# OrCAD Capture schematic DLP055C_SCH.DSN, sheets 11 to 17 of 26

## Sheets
11 P20 - RS232: size A3
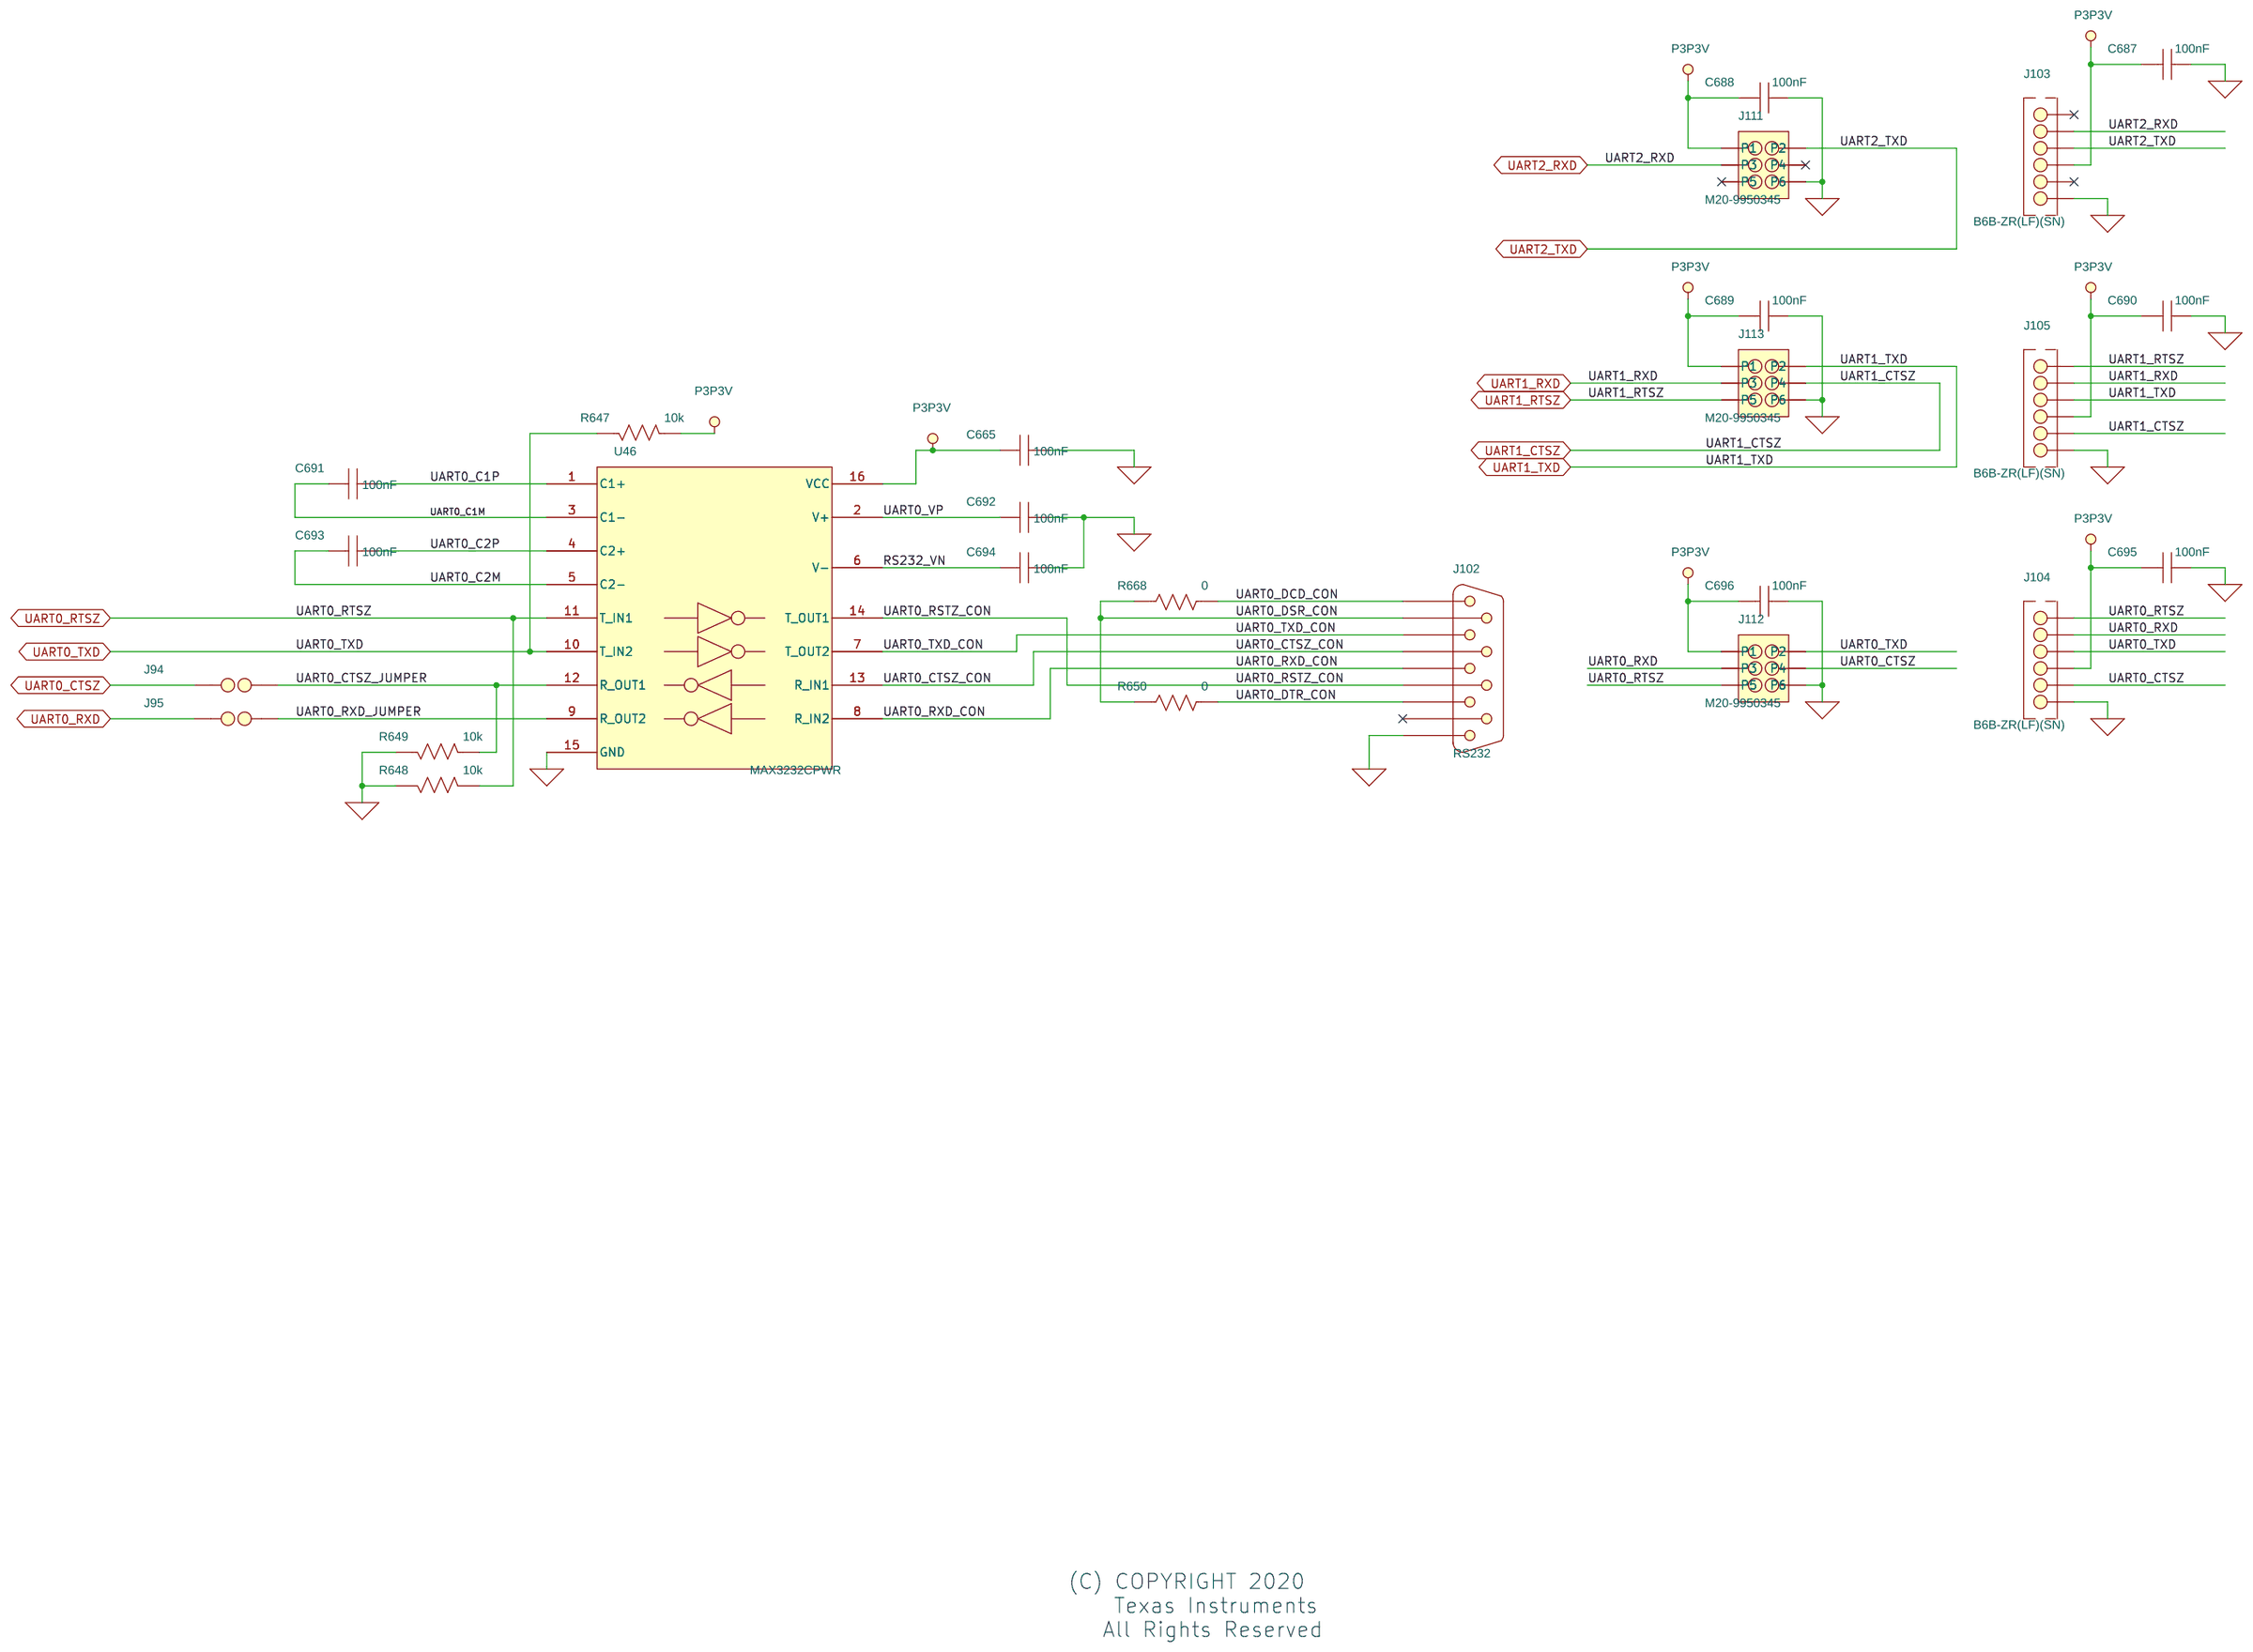
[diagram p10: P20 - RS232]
12 P14 - Actuator Driver: size A2
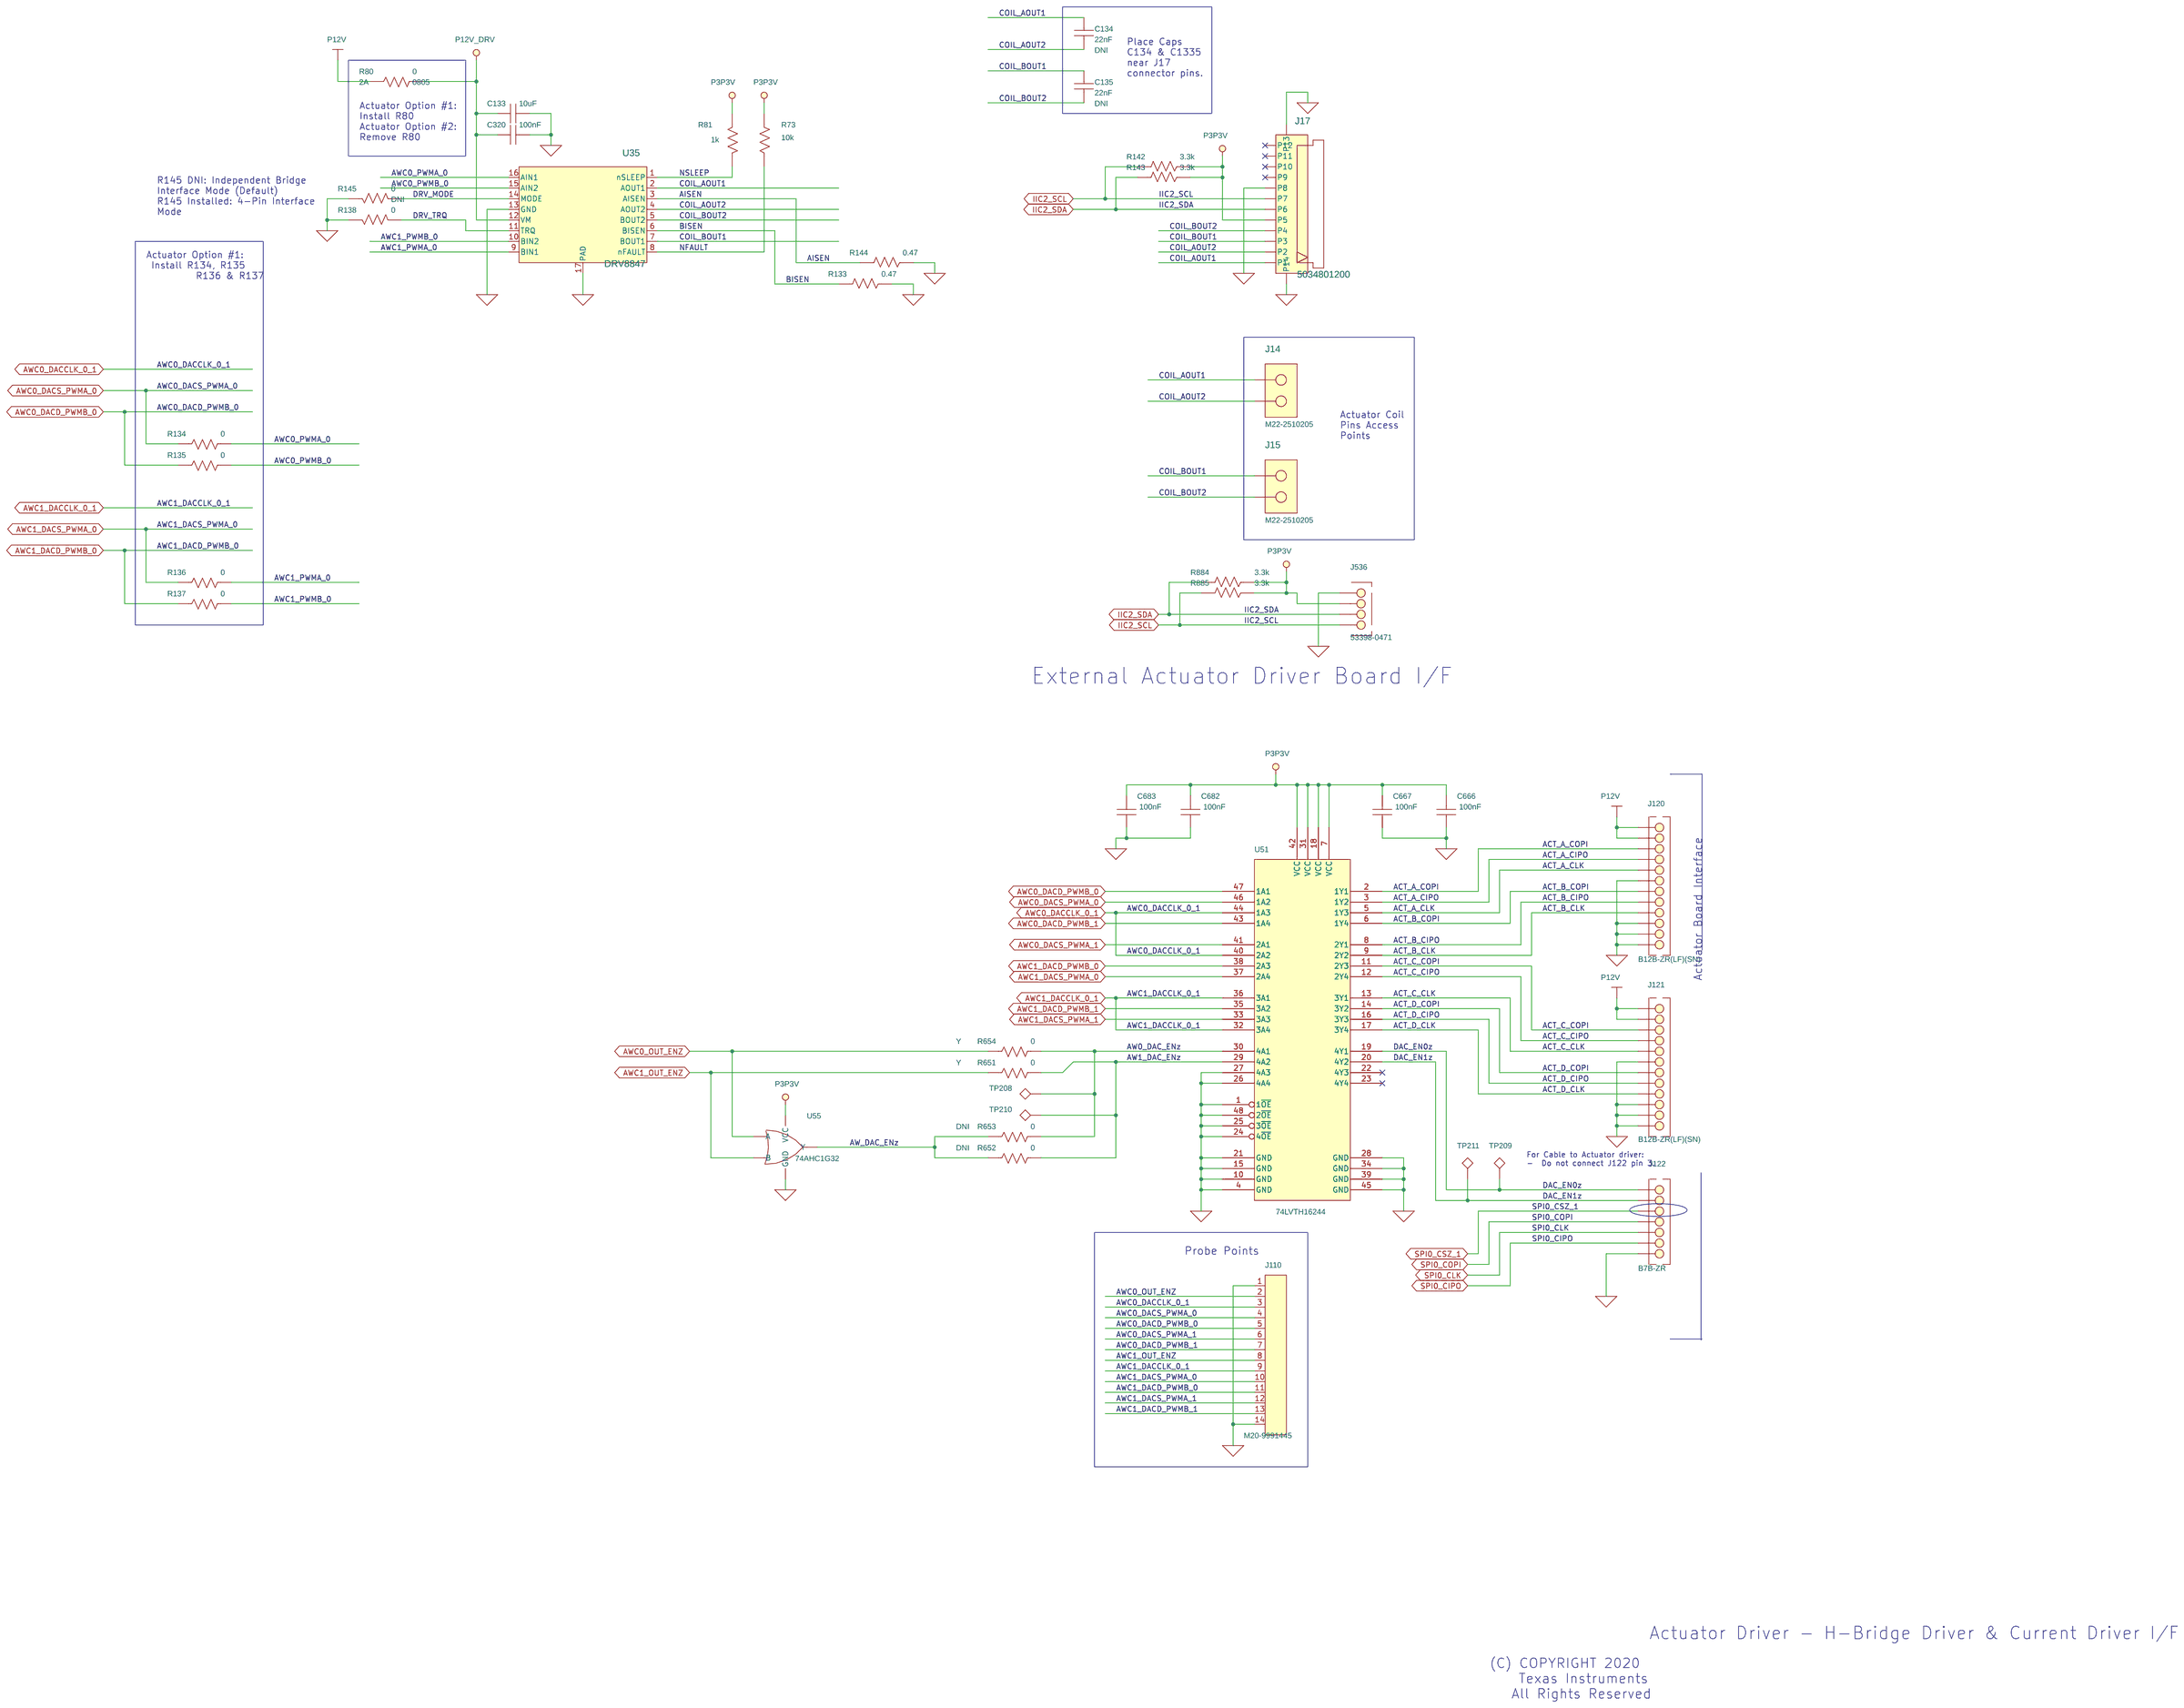
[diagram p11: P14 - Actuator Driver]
13 P01 - TITLE PAGE
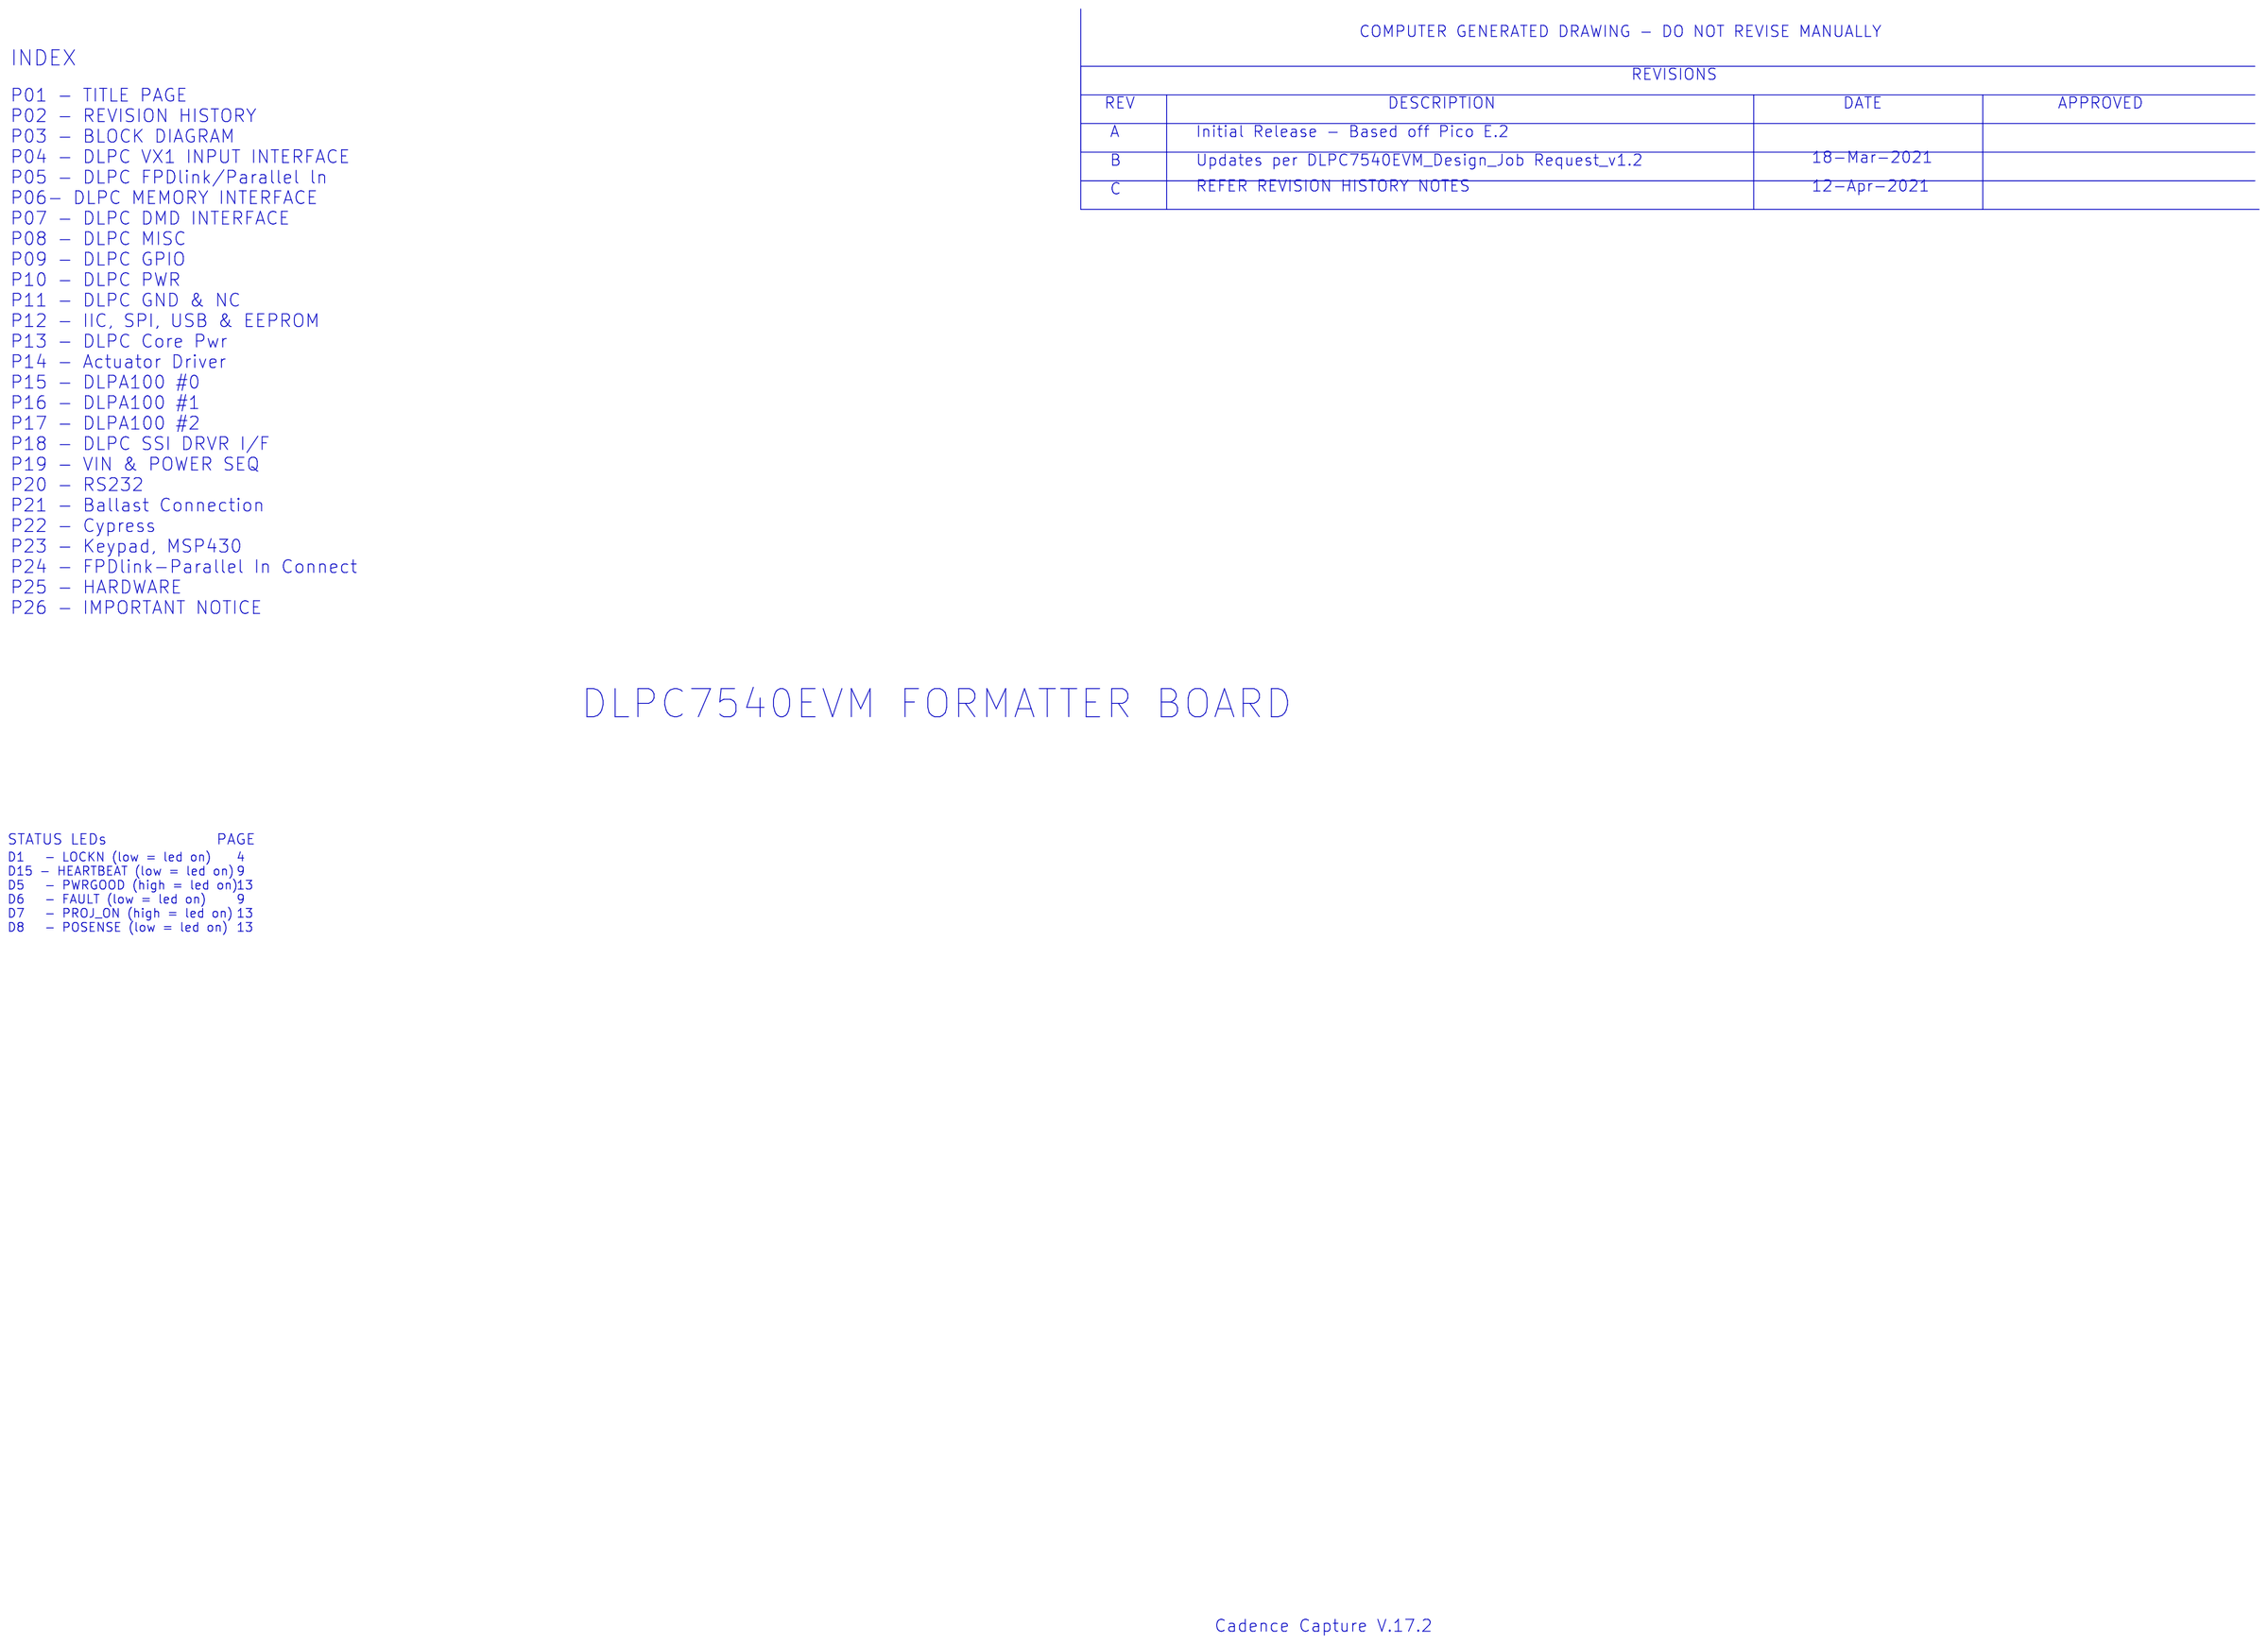
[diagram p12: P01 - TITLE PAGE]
14 P03 - BLOCK DIAGRAM
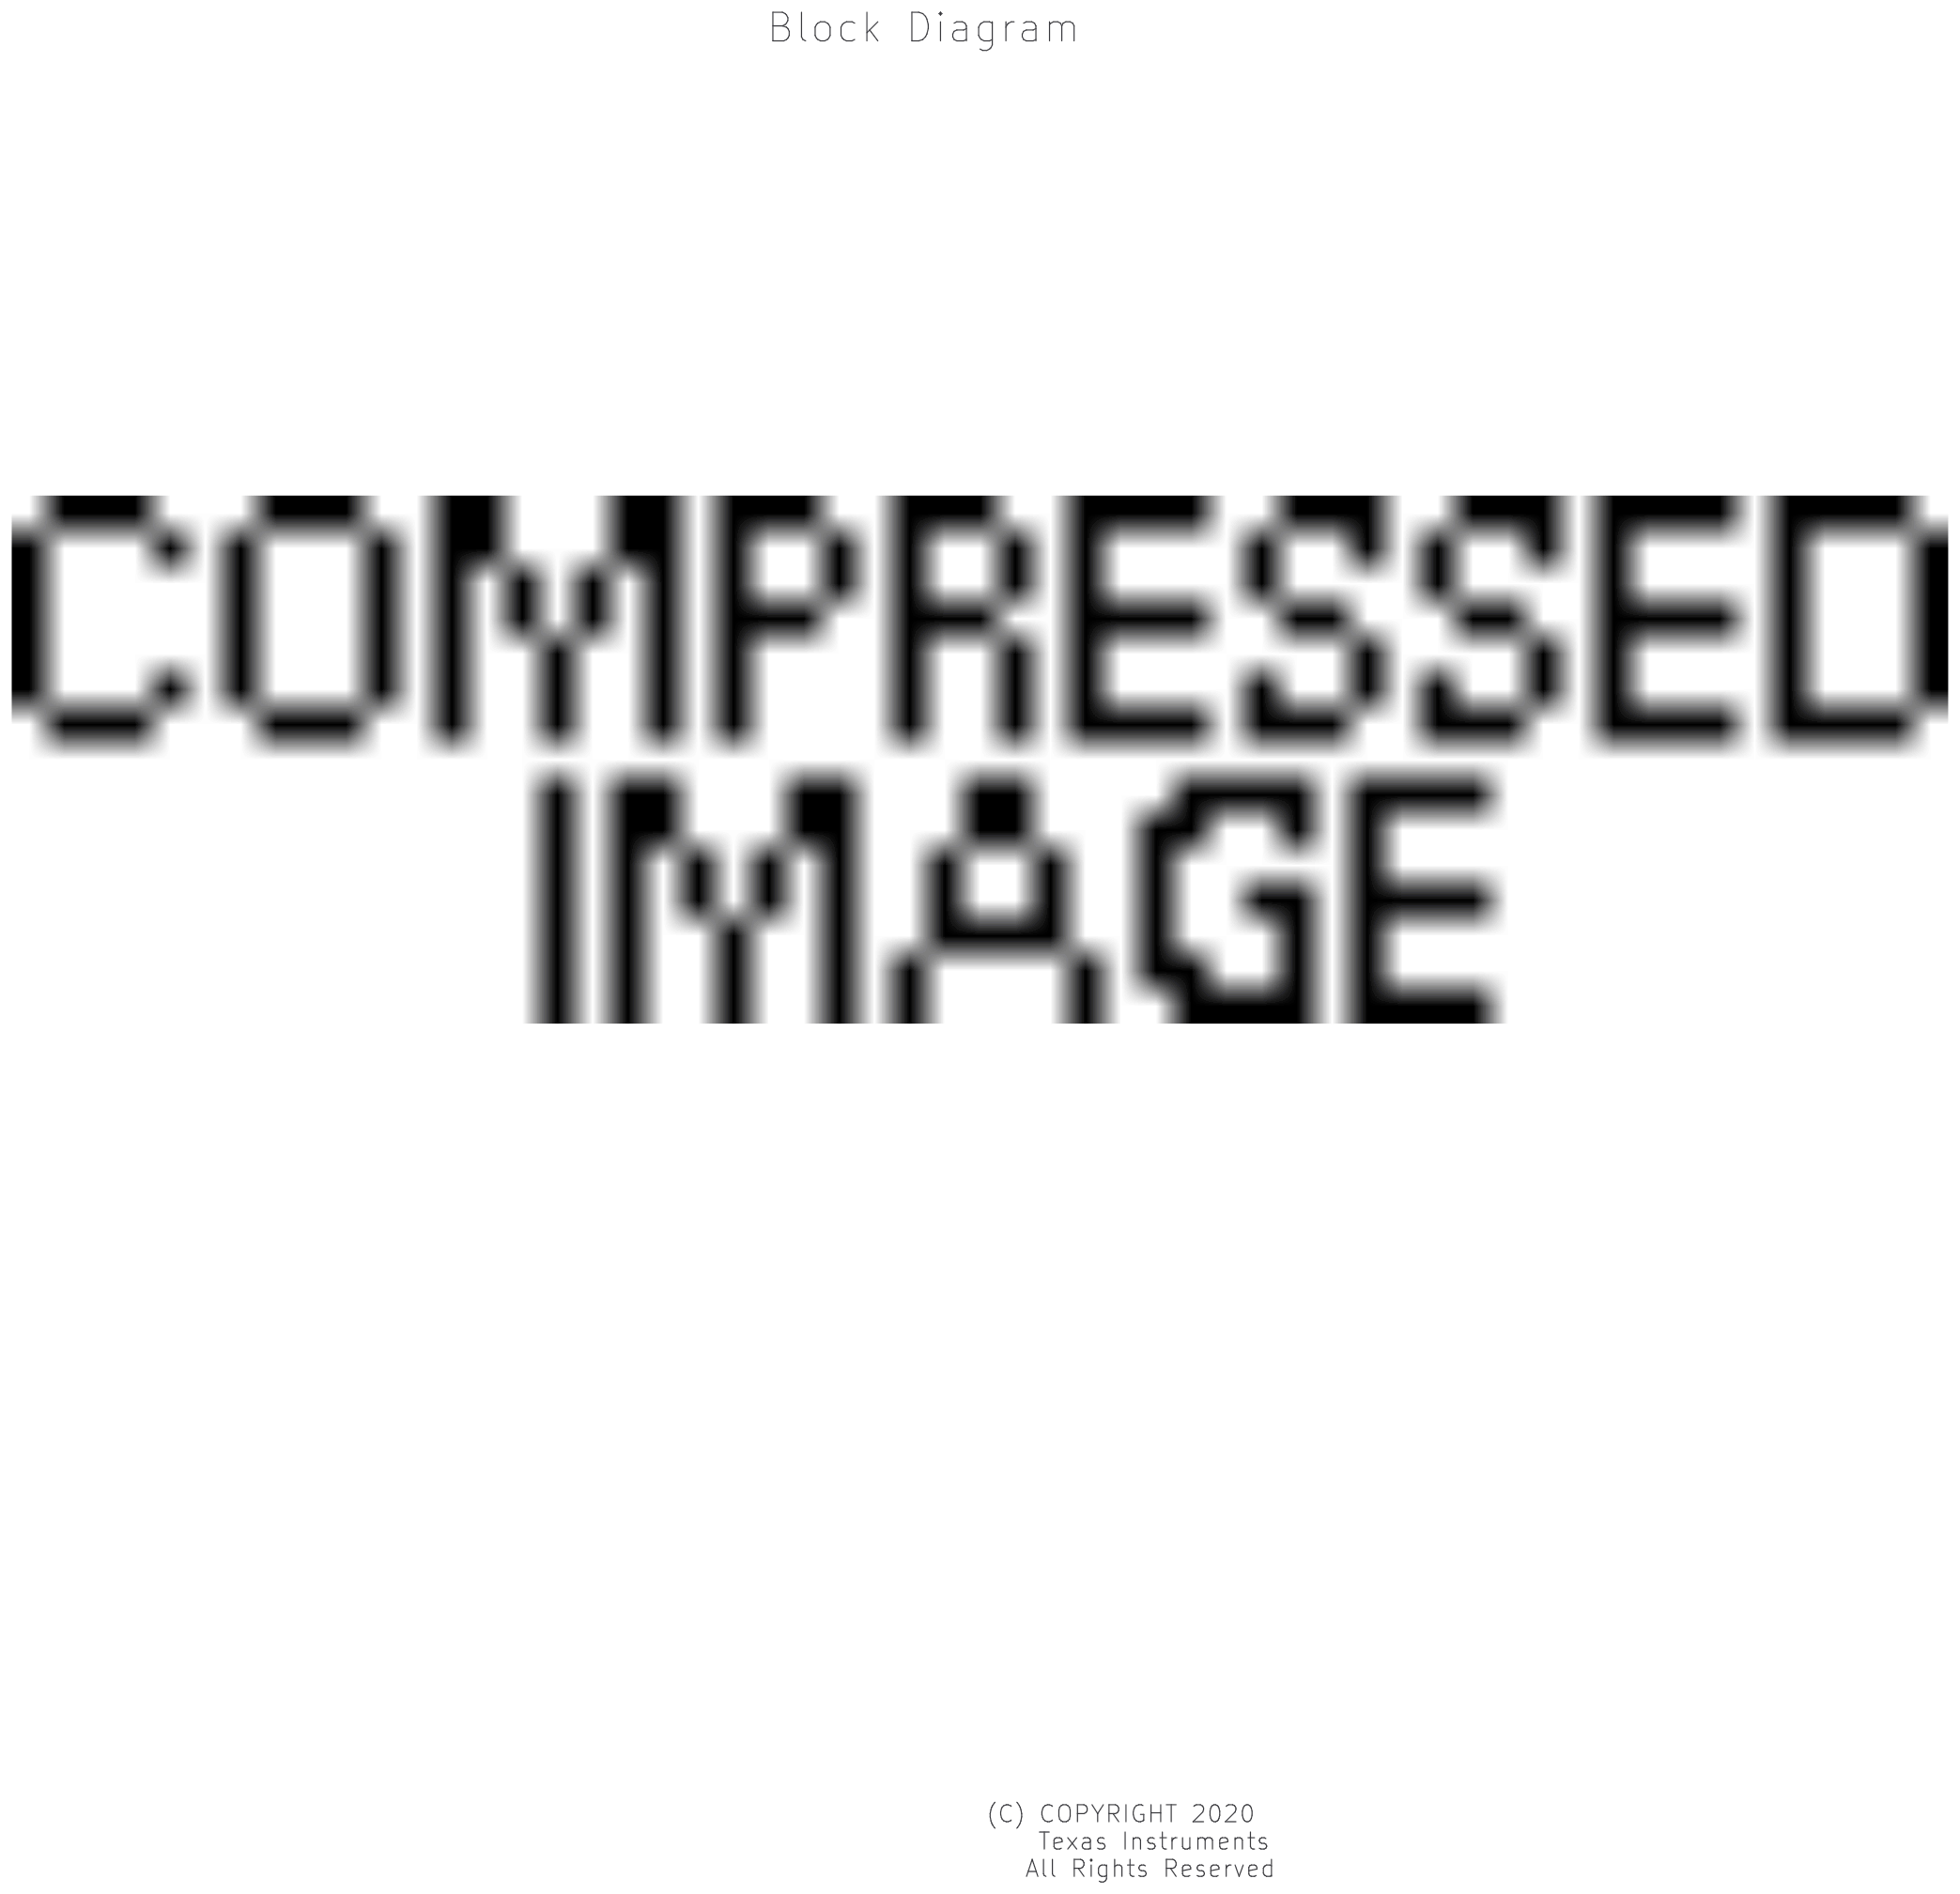
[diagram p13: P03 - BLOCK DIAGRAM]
15 P04 - DLPC VX1 INPUT INTERFACE: size A3
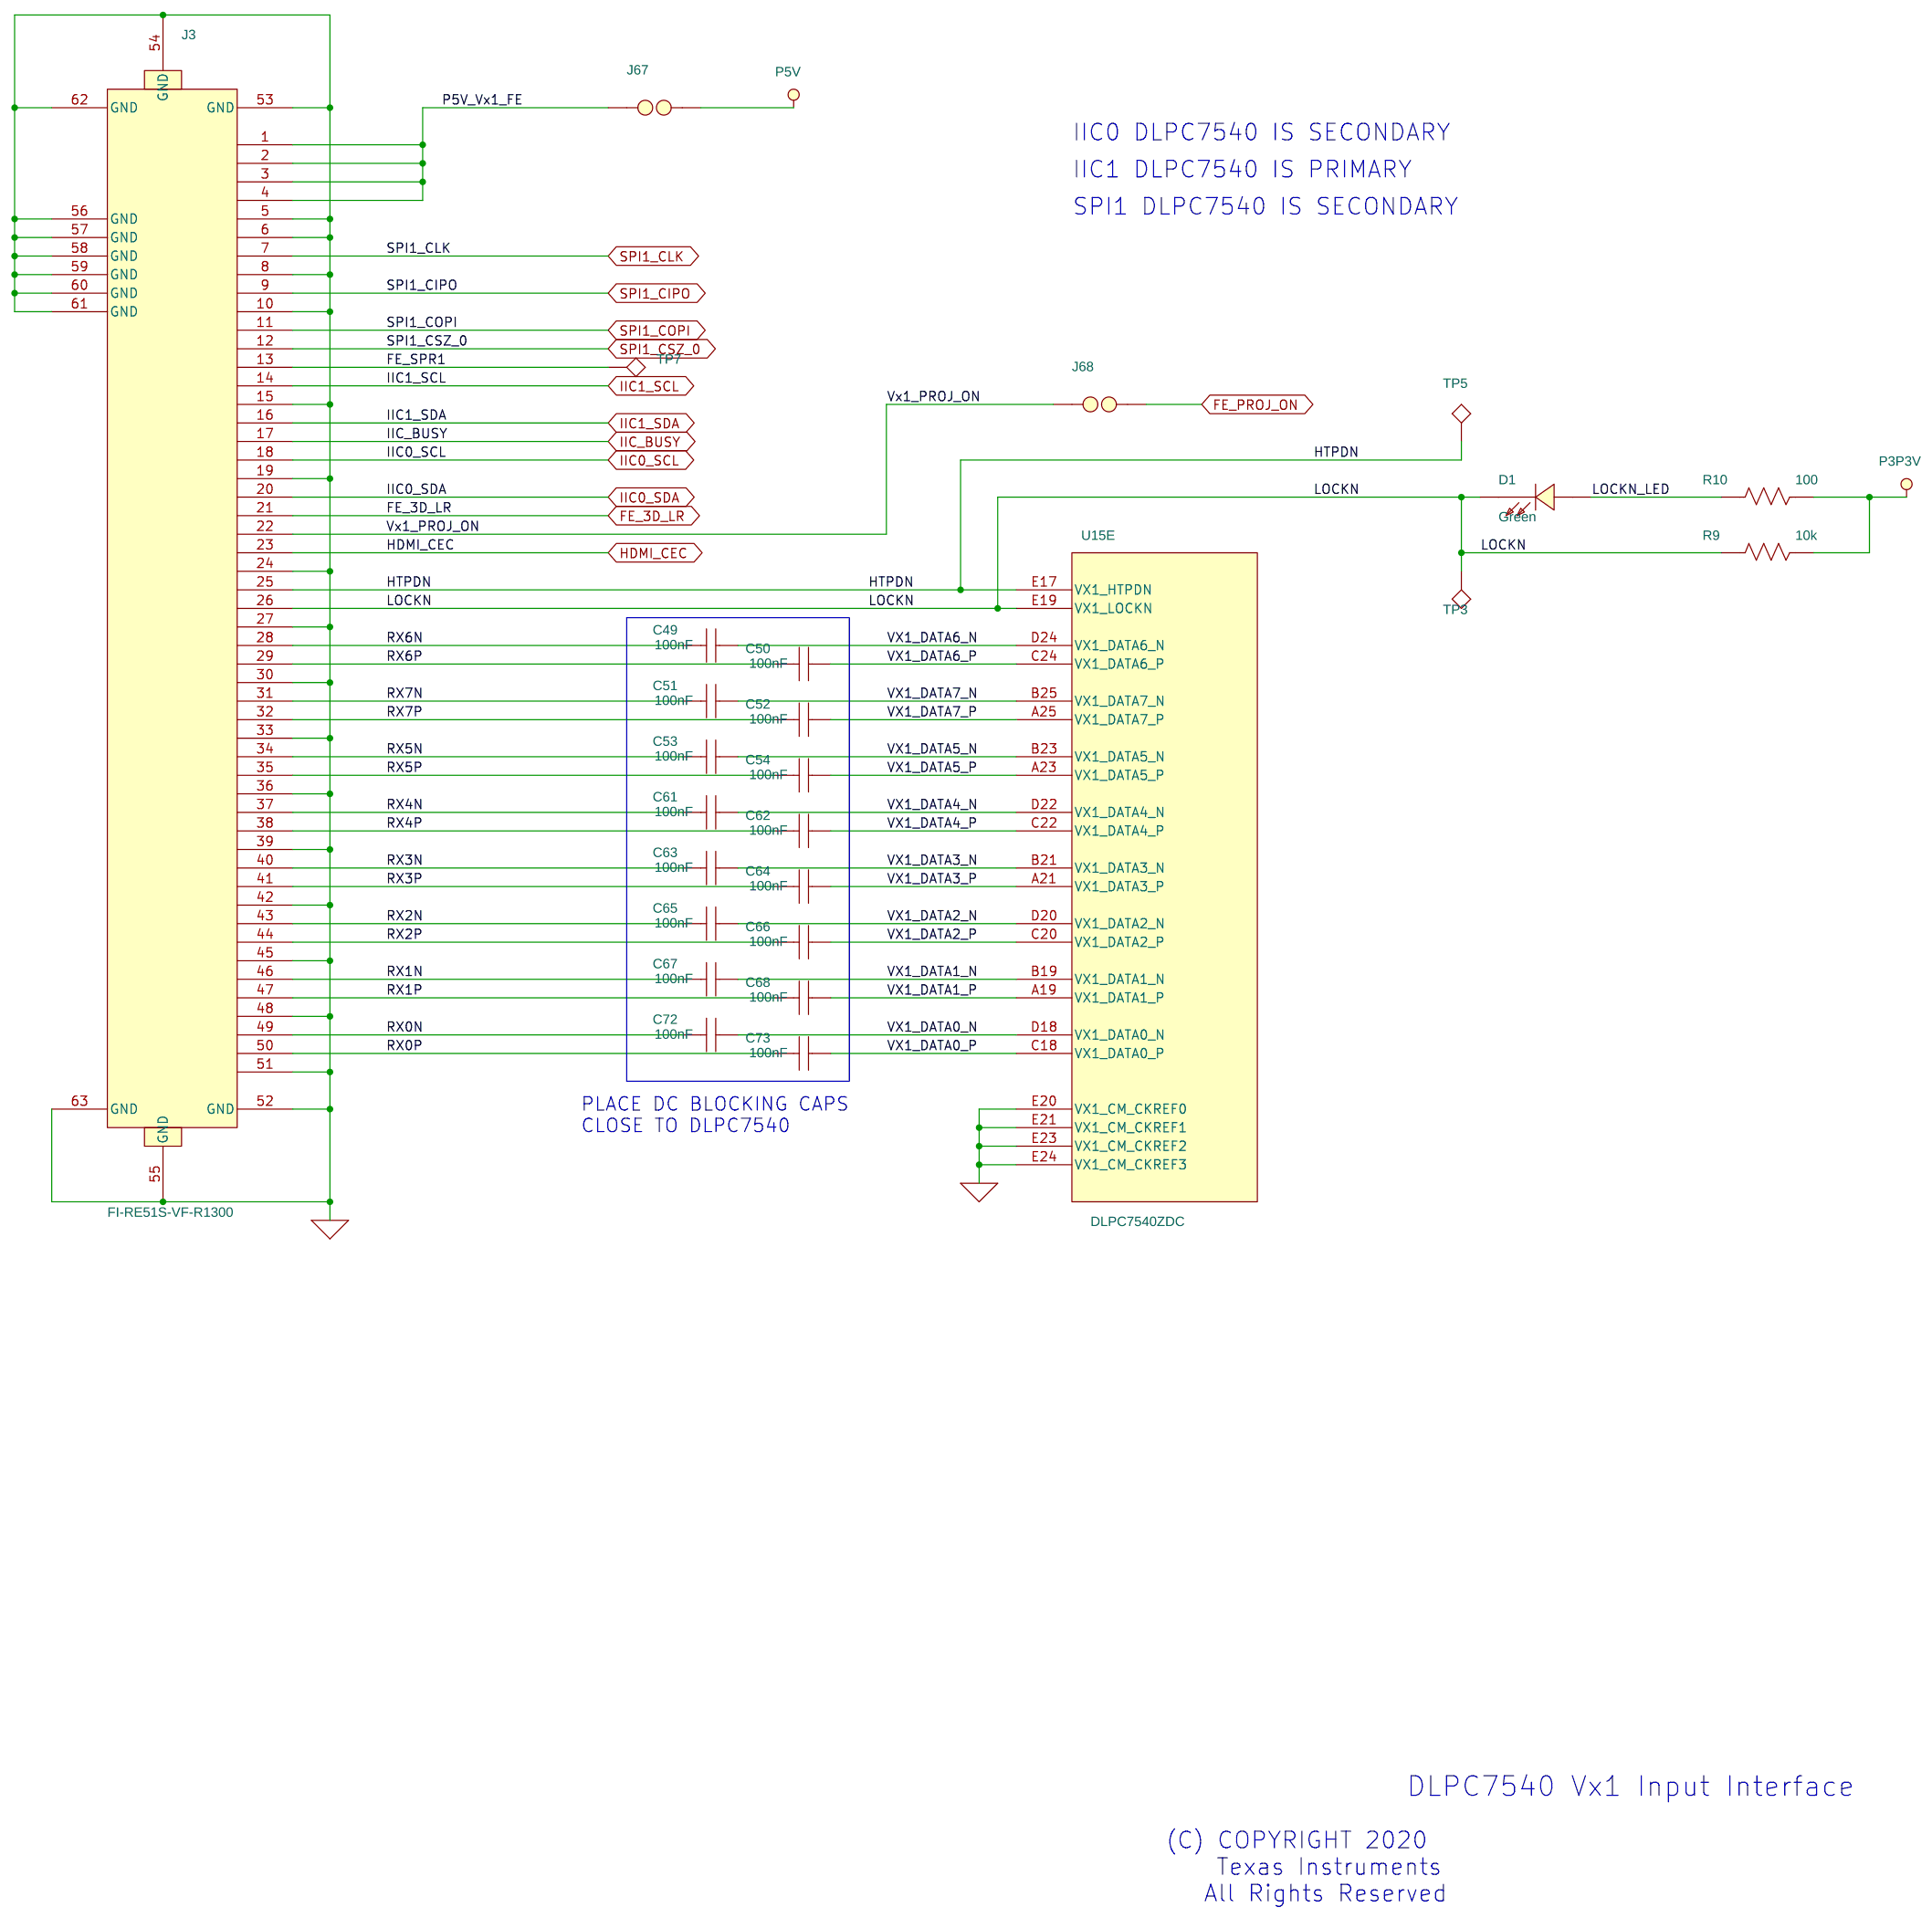
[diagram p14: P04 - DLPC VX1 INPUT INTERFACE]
16 P06- DLPC MEMORY INTERFACE: size A3
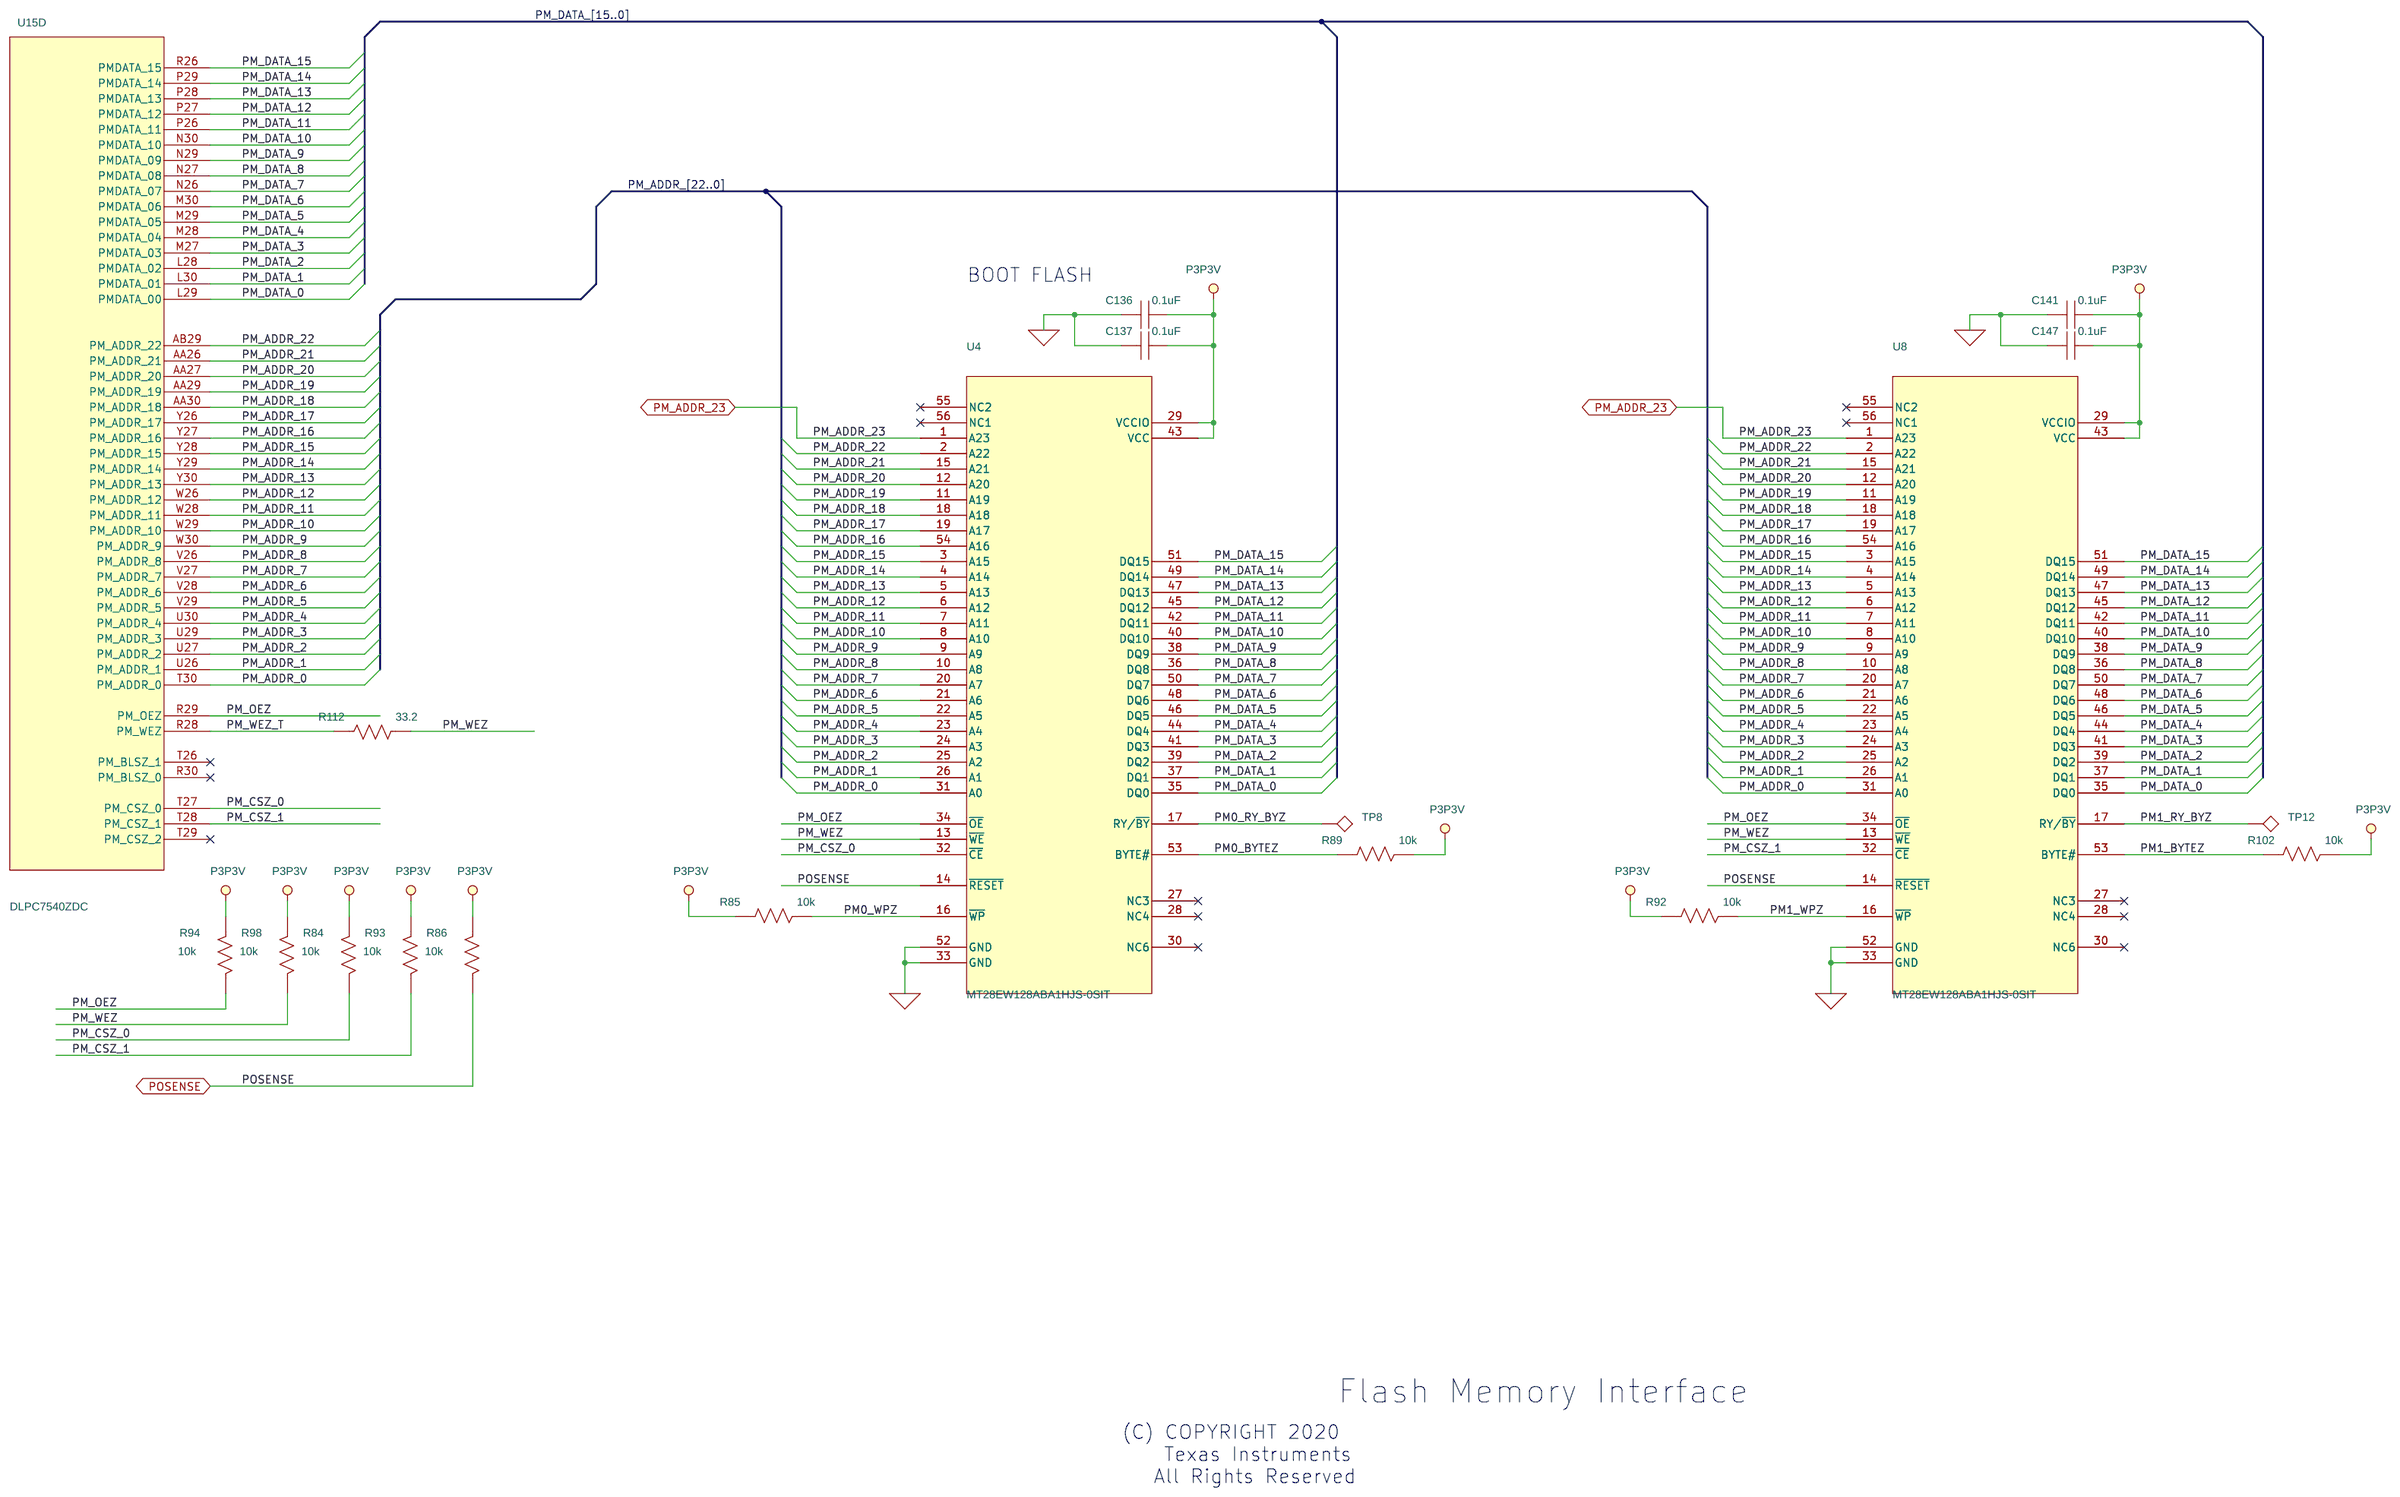
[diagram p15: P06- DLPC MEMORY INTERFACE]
17 P07 - DLPC DMD INTERFACE: size A3
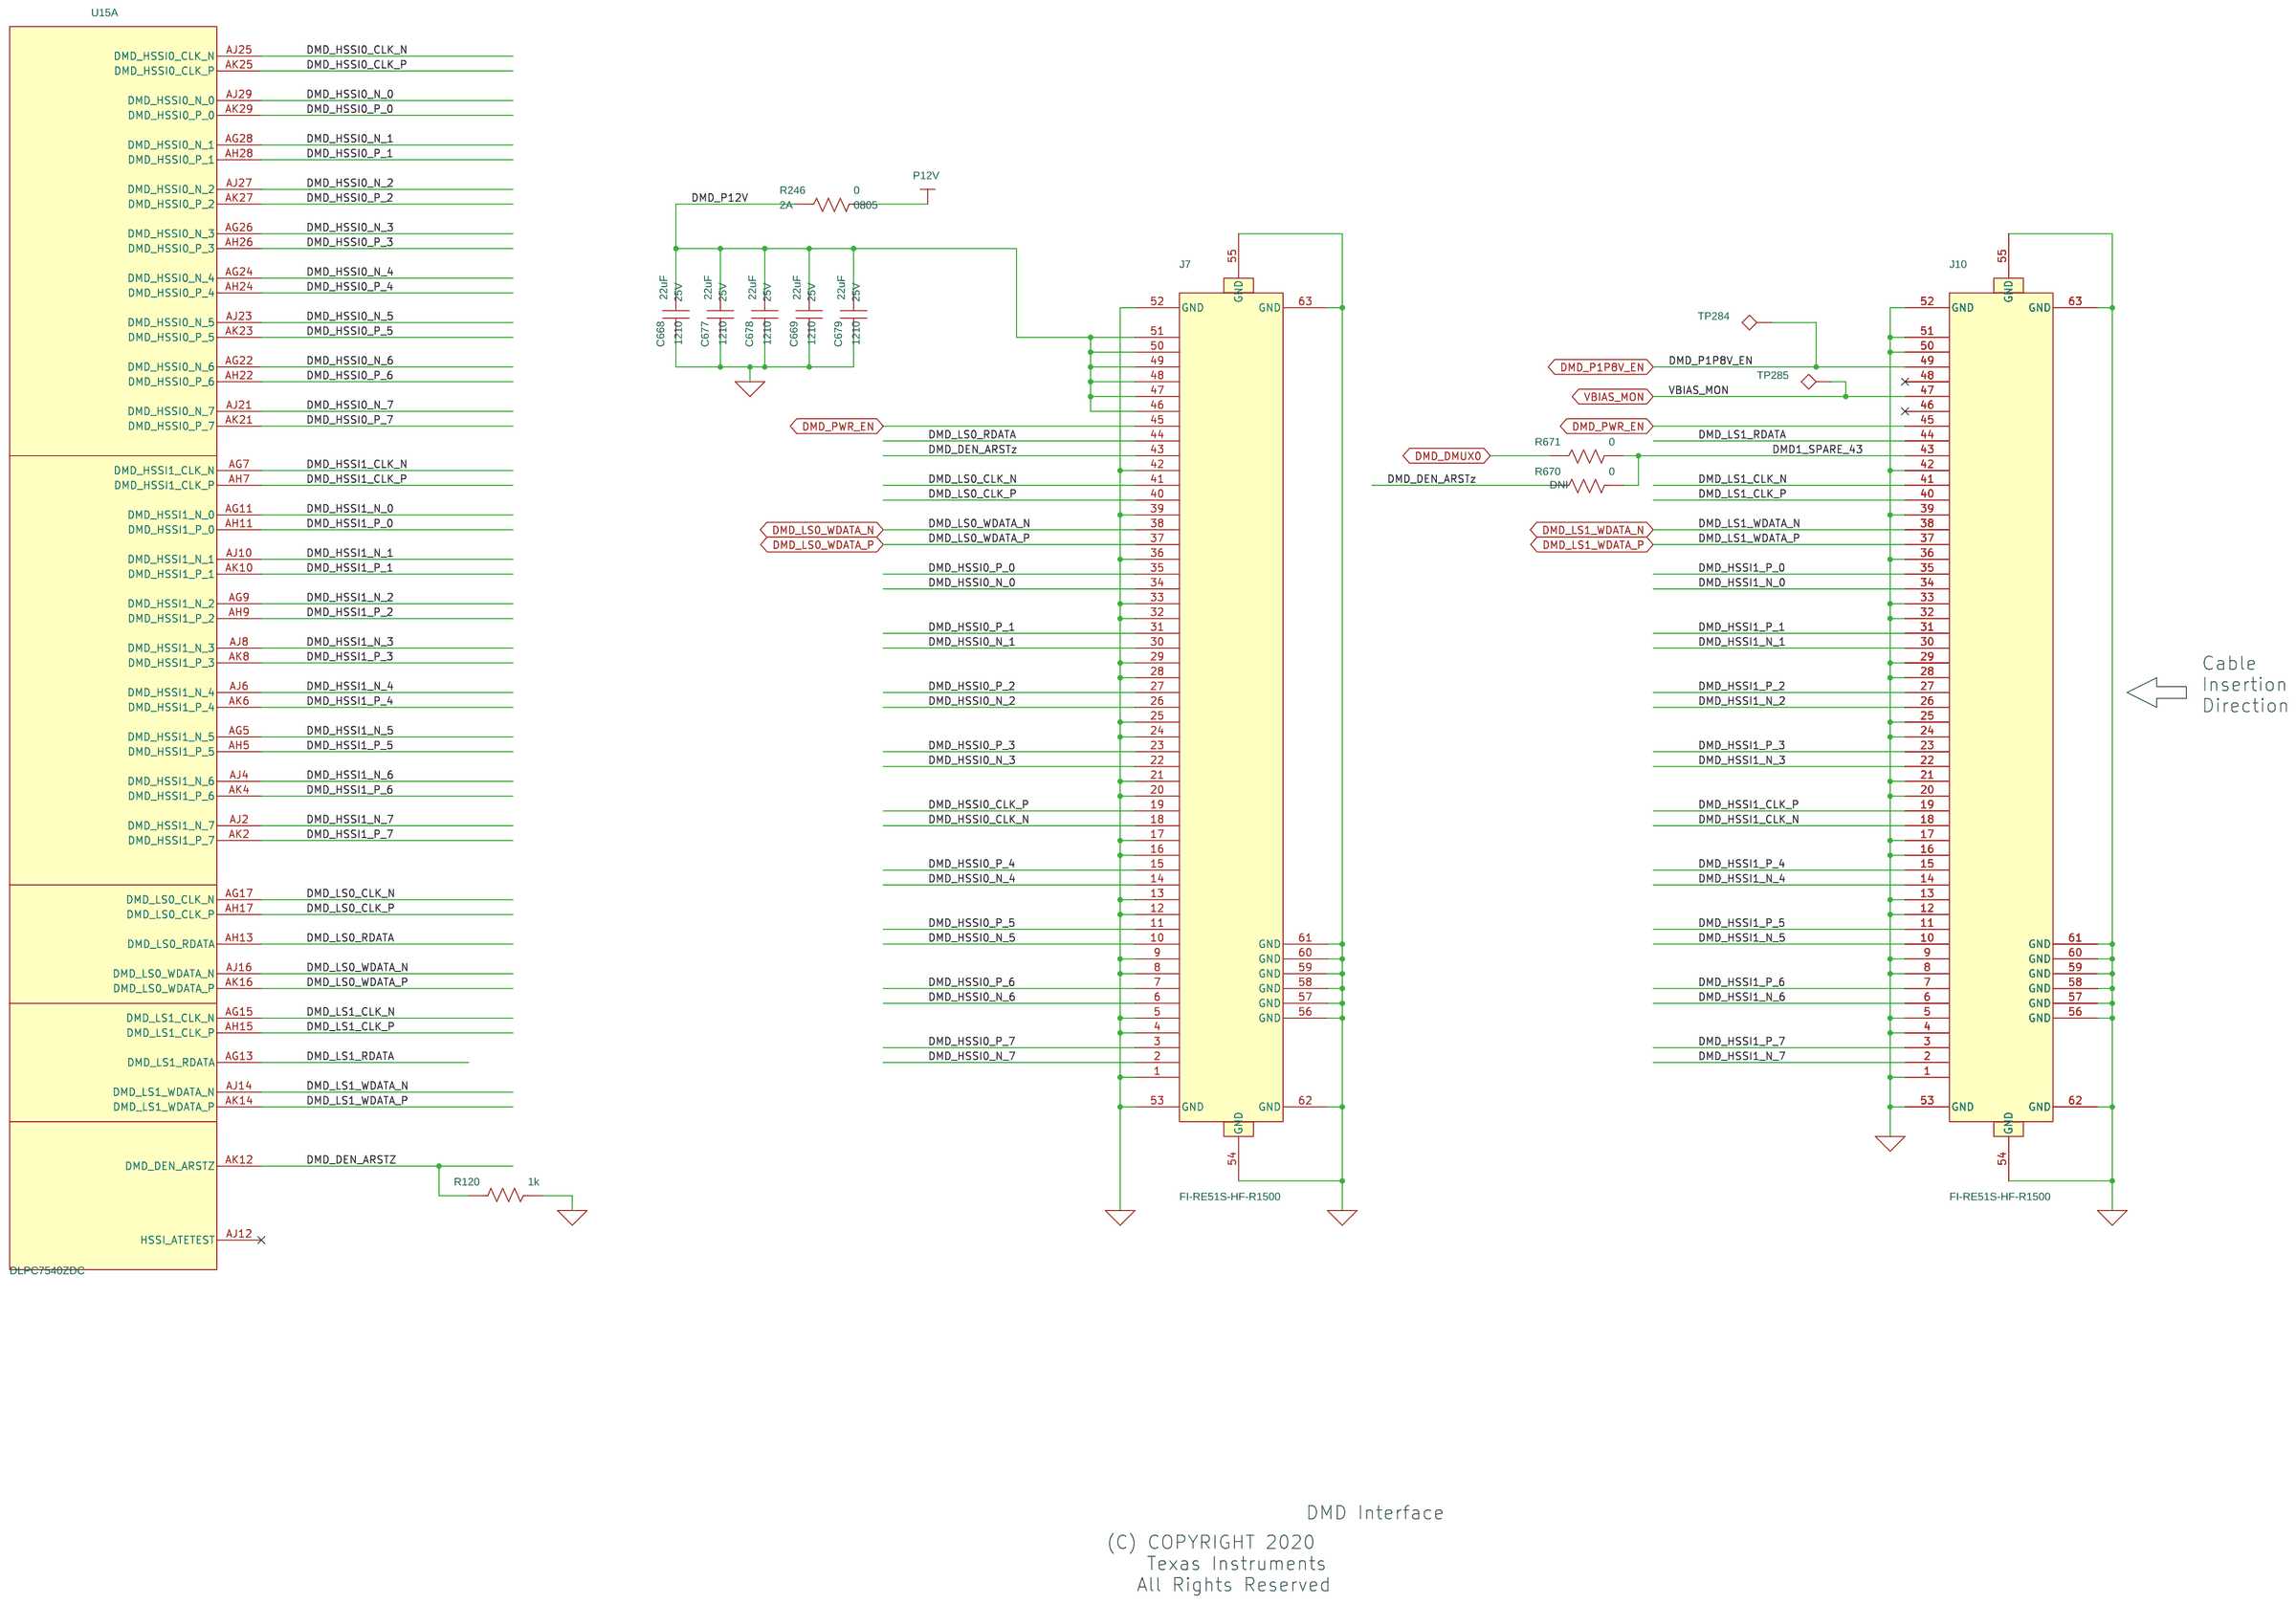
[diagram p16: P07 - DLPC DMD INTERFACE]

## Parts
sheet P04 - DLPC VX1 INPUT INTERFACE
C49  100nF  [0402]
C50  100nF  [0402]
C51  100nF  [0402]
C52  100nF  [0402]
C53  100nF  [0402]
C54  100nF  [0402]
C61  100nF  [0402]
C62  100nF  [0402]
C63  100nF  [0402]
C64  100nF  [0402]
C65  100nF  [0402]
C66  100nF  [0402]
C67  100nF  [0402]
C68  100nF  [0402]
C72  100nF  [0402]
C73  100nF  [0402]
D1  Green  [LED-LTST-C190_LITEON]
J3  FI-RE51S-VF-R1300  [FI-R51-HF_VF_Dual]
J67  HDR,2P,1R  [HDR2P_1R]
J68  HDR,2P,1R  [HDR2P_1R]
R9  10k  [0402]
R10  100  [0402]
TP3  TP,28mil Drill,48mil Pad  [HTP-48RD28]
TP5  TP,28mil Drill,48mil Pad  [HTP-48RD28]
TP7  TP,20mil PAD  [20mil_PAD]
sheet P06- DLPC MEMORY INTERFACE
C136  0.1uF  [0402]
C137  0.1uF  [0402]
C141  0.1uF  [0402]
C147  0.1uF  [0402]
R84  10k  [0402]
R85  10k  [0402]
R86  10k  [0402]
R89  10k  [0402]
R92  10k  [0402]
R93  10k  [0402]
R94  10k  [0402]
R98  10k  [0402]
R102  10k  [0402]
R112  33.2  [0402]
TP8  TP,20mil PAD  [20mil_PAD]
TP12  TP,20mil PAD  [20mil_PAD]
U4  MT28EW128ABA1HJS-0SIT  [SOIC56-TSOP_SPANSION]
U8  MT28EW128ABA1HJS-0SIT  [SOIC56-TSOP_SPANSION]
sheet P07 - DLPC DMD INTERFACE
C668  22uF  [1210]
C669  22uF  [1210]
C677  22uF  [1210]
C678  22uF  [1210]
C679  22uF  [1210]
J7  FI-RE51S-HF-R1500  [FI-R51-HF_VF_Dual]
J10  FI-RE51S-HF-R1500  [FI-R51-HF_VF_Dual]
R120  1k  [0402]
R246  0  [0805]
R670  0  [0402]
R671  0  [0402]
TP284  TP,28mil Drill,48mil Pad  [HTP-48RD28]
TP285  TP,28mil Drill,48mil Pad  [HTP-48RD28]
sheet P09 - DLPC GPIO
U15  TIDLP,DLPC7540  [DLPC7540_HBGA676_3131]  (sections A,B,C,D,E,F,G,H,I)
sheet P14 - Actuator Driver
C133  10uF  [0805]
C134  22nF  [0402]
C135  22nF  [0402]
C320  100nF  [0402]
C666  100nF  [0402]
C667  100nF  [0402]
C682  100nF  [0402]
C683  100nF  [0402]
J14  M22-2510205  [HDR2_2MM]
J15  M22-2510205  [HDR2_2MM]
J17  5034801200  [Molex_5034801200_2GPADS]
J110  HDR,14P,1R  [HDR1X14]
J120  B12B-ZR(LF)(SN)  [HDR1X12-B12B-ZR_JST]
J121  B12B-ZR(LF)(SN)  [HDR1X12-B12B-ZR_JST]
J122  B7B-ZR  [HDR1X7-B7B-ZR_JST]
J536  53398-0471  [CONN4-53398_MOLEX]
R73  10k  [0402]
R80  0  [0805]
R81  1k  [0402]
R133  0.47  [0402]
R134  0  [0402]
R135  0  [0402]
R136  0  [0402]
R137  0  [0402]
R138  0  [0402]
R142  3.3k  [0402]
R143  3.3k  [0402]
R144  0.47  [0402]
R145  0  [0402]
R651  0  [0402]
R652  0  [0402]
R653  0  [0402]
R654  0  [0402]
R884  3.3k  [0402]
R885  3.3k  [0402]
TP208  TP_WHT  [TP_Keystone_5011]
TP209  HDR,1P,1R  [HDR1]
TP210  TP_WHT  [TP_Keystone_5011]
TP211  HDR,1P,1R  [HDR1]
U35  DRV8847  [16HTSSOP_PWP0016C]
U51  74LVTH16244  [SOIC48-DGG_TI]
U55  74AHC1G32  [SOIC5-SOT-23_DBV-TI]
sheet P20 - RS232
C665  100nF  [0402]
C687  100nF  [0402]
C688  100nF  [0402]
C689  100nF  [0402]
C690  100nF  [0402]
C691  100nF  [0402]
C692  100nF  [0402]
C693  100nF  [0402]
C694  100nF  [0402]
C695  100nF  [0402]
C696  100nF  [0402]
J94  HDR,2P,1R  [HDR2P_1R]
J95  HDR,2P,1R  [HDR2P_1R]
J102  RS232  [CONN9-190-009-A_NORCOMP_REV]
J103  B6B-ZR  [HDR1X6-B6B-ZR_JST]
J104  B6B-ZR  [HDR1X6-B6B-ZR_JST]
J105  B6B-ZR  [HDR1X6-B6B-ZR_JST]
J111  HDR,6P,2R,RA  [HDR-2X3-a-RA]
J112  HDR,6P,2R,RA  [HDR-2X3-a-RA]
J113  HDR,6P,2R,RA  [HDR-2X3-a-RA]
R647  10k  [0402]
R648  10k  [0402]
R649  10k  [0402]
R650  0  [0402]
R668  0  [0402]
U46  MAX3232CPWR  [SOIC16-PW_TI]

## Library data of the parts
C49-C54 C61-C68 C72 C73 = CER_0.1UF_16V_10%_X5R_0402: ALT_SYMBOLS: 0402_1mm; DigiKey: 587-3499-1-ND; DigiReel: 587-3499-6-ND; Family: passive; Index PN: 1280; Install: Y; Lead Style: SMT; MFG: Taiyo Yuden; Material: x5r; P/D_NUM: UMK105BJ104KV-F; Part Number: UMK105BJ104KV-F; Part Specific: CAP CER 0.1UF 50V 10% X5R 0402; Type: capacitor; VPC: 50V; Vendor: Taiyo Yuden
D1 = PAS,DIODE,LED,ALT: DigiKey: 160-1183-1-ND; DigiReel: 160-1183-6-ND; Family: passive; Index PN: 1451; Install: Y; Lead Style: SMT; MFG: Liteon; P/D_NUM: LTST-C190GKT; Part Number: LTST-C190GKT; Part Specific: LED GREEN CLEAR 0603 SMD; Type: diode,led; Vendor: Liteon
J3 = TMP_154138: DigiKey: 670-2149-1-ND; DigiReel: 670-2149-6-ND; Family: electro/mechanical; Index PN: 1629; Lead Style: SMT; MFG: JAE; Part Specific: CONN RCPT 51POS 0.02 GOLD SMD; Pin Cnt: 51; Type: connector; Vendor: JAE
J67 J68 J94 J95 = EM,JMP,2P,1R: DigiKey: 952-2261-ND; Index PN: 180; Lead Style: TH; MFG: Harwin; P/D_NUM: M20-9990245; Part Number: M20-9990245; Part Specific: 2 Positions Header  Unshrouded  Breakaway Connector 0.100in (2.54mm) Through Hole Gold; Pin Cnt: 2; Pin Spacing: 100mil; Row Cnt: 1; Type: header; Vendor: Harwin
R9 = PAS,R,large: ALT_SYMBOLS: 0402_1mm; DigiKey: 311-10.0KLRCT-ND; DigiReel: 311-10.0KLRDKR-ND; Family: passive; ICA_MFR_NAME: PANASONIC; ICA_PARTNUM: $$1785048$$ERJ-3GSYJ102; Index PN: 680; Install: Y; Lead Style: SMT; MFG: Yageo; Material: chip; P/D_NUM: RC0402FR-0710KL; Part Number: RC0402FR-0710KL; Part Specific: RES 10K OHM 1% 1/16W 0402 SMD; Power: 1/16W; TOLERANCE: 1%; Type: resistor; VPC: 1/16W; Vendor: Yageo
R10 = PAS,R,large: ALT_SYMBOLS: 0402_1mm; DigiKey: P100LCT-ND; DigiReel: P100LDKR-ND; Family: passive; ICA_MFR_NAME: PANASONIC; ICA_PARTNUM: $$1785048$$ERJ-3GSYJ102; Index PN: 690; Install: Y; Lead Style: SMT; MFG: Panasonic; Material: chip; P/D_NUM: ERJ-2RKF1000X; Part Number: ERJ-2RKF1000X; Part Specific: RES 100 OHM 1% 1/10W 0402 SMD; Power: 1/16W; TOLERANCE: 1%; Type: resistor; VPC: 1/16W; Vendor: Panasonic
TP3 TP5 TP284 TP285 = EM,TERM,TESTPOINT: DigiKey: ---; Family: board feature; Index PN: 1498; Install: DNI; Lead Style: TH; MFG: -- NOT A PART --; Part Specific: HOLE PLATED 48mil pad 28mil drill; Type: hole,plated; Vendor: -- NOT A PART --
TP7 TP8 TP12 = EM,TERM,TESTPOINT: Family: board feature; Index PN: 1145; Install: DNI; Lead Style: SMT; MFG: -- NOT A PART --; Type: pad pattern; Vendor: -- NOT A PART --
C136 C137 C141 C147 = PAS,CAP,NP: DigiKey: 587-3499-1-ND; DigiReel: 587-3499-6-ND; Family: passive; Install: Y; Lead Style: SMT; MFG: Taiyo Yuden; Material: x5r; P/D_NUM: UMK105BJ104KV-F; Part Number: UMK105BJ104KV-F; Part Specific: CAP CER 0.1UF 50V 10% X5R 0402; TOLERANCE: 10%; Type: capacitor; VPC: 50V; Vendor: Taiyo Yuden; Voltage: 50V
R84-R86 R89 R92-R94 R98 R102 = PAS,R,large: DigiKey: 311-10.0KLRCT-ND; DigiReel: 311-10.0KLRDKR-ND; Family: passive; Index PN: 680; Lead Style: SMT; MFG: Yageo; Material: chip; P/D_NUM: RC0402FR-0710KL; Part Number: RC0402FR-0710KL; Part Specific: RES 10K OHM 1% 1/16W 0402 SMD; Power: 1/16W; Tolerance: 1%; Type: resistor; VPC: 1/16W; Vendor: Yageo
R112 = PAS,R,large: ALT_SYMBOLS: 0402_1mm; CCA: 67; DigiKey: P33.2LCT-ND; Family: passive; Index PN: 725; Install: Y; MFG: Panasonic; Material: chip; P/D_NUM: ERJ-2RKF33R2X; Part Number: ERJ-2RKF33R2X; Part Specific: RES 33.2 OHM 1/16W 1% 0402 SMD; Power: 1/16W; TOLERANCE: 1%; Type: resistor; VPC: 1/16W; Vendor: Panasonic
U4 U8 = MEM,FLASH,256Mb,x16,TSOP-56: DigiKey: 557-1776-ND; Index PN: 1478; Lead Style: SMT; MFG: Micron; Part Specific: IC FLASH 128MBIT 70NS 56TSOP; VPC: 2.7-3.6V; Vendor: Micron
C668 C669 C677-C679 = PAS,CAP,NP: CCA: 115; DigiKey: 587-2086-1-ND; Family: passive; Index PN: 1406; Install: Y; Lead Style: SMT; MFG: Taiyo Yuden; Material: x5r; P/D_NUM: TMK325BJ226MM-T; Part Number: TMK325BJ226MM-T; Part Specific: CAP CER 22UF 25V X5R 1210; TOLERANCE: 20%; Type: capacitor; VPC: 25V; Vendor: Taiyo Yuden
J7 J10 = TMP_154138: DigiKey: 670-1206-1-ND; DigiReel: 670-1206-6-ND; Family: electro/mechanical; Index PN: 1629; Lead Style: SMT; MFG: JAE; Part Specific: CONN RCPT 51POS 0.02 GOLD SMD R/A; Pin Cnt: 51; Type: connector; Vendor: JAE
R120 = PAS,R,large: ALT_SYMBOLS: 0402_1mm; DigiKey: P1.00KLCT-ND; DigiReel: P1.00KLDKR-ND; Family: passive; Index PN: 684; Lead Style: SMT; MFG: Panasonic; Material: chip; P/D_NUM: ERJ-2RKF1001X; Part Number: ERJ-2RKF1001X; Part Specific: RES 1.00K OHM 1/10W 1% 0402 SMD; Power: 1/16W; Tolerance: 1%; Type: resistor; VPC: 1/16W; Vendor: Panasonic
R246 = PAS,R,large: CCA: 62; DigiKey: P0.0ACT-ND; Family: passive; ICA_MFR_NAME: PANASONIC; ICA_PARTNUM: $$1785048$$ERJ-3GSYJ102; Index PN: 160; Install: Y; MFG: Panasonic; Material: chip; P/D_NUM: ERJ6GEY0R00V; Part Number: ERJ6GEY0R00V; Part Specific: RES 0.0 OHM 1/8W 0805 SMD 2A; Power: 1/8w; Type: resistor; VPC: 2A; Vendor: Panasonic
R652 R653 R670 = PAS,R,large: ALT_SYMBOLS: 0402_1mm; CCA: 62; DigiKey: P0.0JCT-ND; Family: passive; ICA_MFR_NAME: PANASONIC; ICA_PARTNUM: $$1785048$$ERJ-3GSYJ102; Index PN: 687; Install: DNI; Lead Style: SMT; MFG: Panasonic; Material: chip; P/D_NUM: ERJ-2GE0R00X; Part Number: ERJ-2GE0R00X; Part Specific: RES 0.0 OHM 1/16W 0402 SMD; Power: 1/16W; Type: resistor; VPC: 1/16W; Vendor: Panasonic
R650 R651 R654 R668 R671 = PAS,R,large: ALT_SYMBOLS: 0402_1mm; CCA: 62; DigiKey: P0.0JCT-ND; Family: passive; ICA_MFR_NAME: PANASONIC; ICA_PARTNUM: $$1785048$$ERJ-3GSYJ102; Index PN: 687; Install: Y; Lead Style: SMT; MFG: Panasonic; Material: chip; P/D_NUM: ERJ-2GE0R00X; Part Number: ERJ-2GE0R00X; Part Specific: RES 0.0 OHM 1/16W 0402 SMD; Power: 1/16W; Type: resistor; VPC: 1/16W; Vendor: Panasonic
U15 = TIDLP,DLPC7540: MFG: Texas Instruments; Part Number: DLPC7540ZDC
C133 = PAS,CAP,NP: DigiKey: 587-2985-1-ND; DigiReel: 587-2985-6-ND; Family: passive; Lead Style: SMT; MFG: Taiyo Yuden; Material: x5r; P/D_NUM: TMK212BBJ106KG-T; Part Number: TMK212BBJ106KG-T; Part Specific: CAP CER 10UF 25V 10% X5R 0805; Tolerance: 10%; VPC: 25V; Vendor: Taiyo Yuden; Voltage: 25V
C134 C135 = PAS,CAP,NP: ALT_SYMBOLS: 0402_1mm; DigiKey: 587-1224-1-ND; DigiReel: 587-1224-6-ND; Family: passive; Index PN: 1116; Install: DNI; Lead Style: SMT; MFG: Taiyo Yuden; Material: x7r; P/D_NUM: EMK105B7223KV-F; Part Number: EMK105B7223KV-F; Part Specific: CAP CER 0.022UF 16V 10% X7R 0402; Tolerance: 10%; VPC: 16V; Vendor: Taiyo Yuden
C320 = PAS,CAP,NP: ALT_SYMBOLS: 0402_1mm; DigiKey: 587-3499-1-ND; DigiReel: 587-3499-6-ND; Family: passive; Index PN: 1280; Lead Style: SMT; MFG: Taiyo Yuden; Material: x5r; P/D_NUM: UMK105BJ104KV-F; Part Number: UMK105BJ104KV-F; Part Specific: CAP CER 0.1UF 50V 10% X5R 0402; Tolerance: 10%; VPC: 50V; Vendor: Taiyo Yuden; Voltage: 50V
C666 C667 C682 C683 = PAS,CAP,NP: ALT_SYMBOLS: 0402_1mm; CCA: 5; DigiKey: 587-3499-1-ND; Family: passive; Index PN: 1280; Install: Y; Lead Style: SMT; MFG: Taiyo Yuden; Material: x5r; P/D_NUM: UMK105BJ104KV-F; Part Number: UMK105BJ104KV-F; Part Specific: CAP CER 0.1UF 50V 10% X5R 0402; TOLERANCE: 10%; Type: capacitor; VPC: 50V; Vendor: Taiyo Yuden
J14 = HDR_2: Jumper, 1x2; DigiKey: 952-1311-ND; DigiReel: ---; Family: electro/mechanical; Index PN: 1524; Install: Y; Lead Style: TH; MFG: Harwin; Part Specific: CONN HEADER 2MM VERT AU 2POS; Pin Cnt: 2; Pin Spacing: 2mm; Row Cnt: 1; SOURCE: DIGI 952-1311-ND; Type: header; Vendor: Harwin
J15 = HDR_2: Jumper, 1x2; CCA: 128; DigiKey: 952-1311-ND; DigiReel: ---; Family: electro/mechanical; Index PN: 1524; Install: Y; Lead Style: TH; MFG: Harwin; Part Specific: CONN HEADER 2MM VERT AU 2POS; Pin Cnt: 2; Pin Spacing: 2mm; Row Cnt: 1; SOURCE: DIGI 952-1311-ND; Type: header; Vendor: Harwin
J17 = EM,CONN,12P+2G,1R,FLEX,1x: DigiKey: WM1441CT-ND; DigiReel: WM1441DKR-ND; Family: electro/mechanical; Lead Style: SMT; MFG: Molex; Part Specific: CONN FFC FPC 12POS 0.50MM R/A; Pin Cnt: 12; Pin Spacing: 0.5mm; Row Cnt: 1; Type: connector; Vendor: Molex
J110 = EM,HDR,14P,1R: DigiKey: M20-9991445-ND; Family: electro/mechanical; Index PN: 144; Install: Y; Lead Style: TH; MFG: Harwin; P/D_NUM: M20-9991445; Part Number: M20-9991445; Part Specific: CONN HEADER VERT 14POS 2.54MM; Pin Cnt: 14; Pin Spacing: 100mil; Row Cnt: 1; Type: header; Vendor: Harwin
J120 J121 = EM,HDR,12P,1R,1x,B12B-EH: DigiKey: 455-1667-ND; Family: electro/mechanical; Index PN: 1512; Lead Style: TH; MFG: JST; Part Specific: CONN HEADER ZH TOP 12POS 1.5MM; Pin Cnt: 12; Pin Spacing: 1.5mm; Row Cnt: 1; Type: header; Vendor: JST
J122 = EM,HDR,7P,1R,1x,B7B-EH: DigiKey: 455-1662-ND; Family: electro/mechanical; Index PN: 1513; Lead Style: TH; MFG: JST; P/D_NUM: B7B-ZR(LF)(SN); Part Number: B7B-ZR(LF)(SN); Part Specific: CONN HEADER ZH TOP 7POS 1.5MM; Pin Cnt: 7; Pin Spacing: 1.5mm; Row Cnt: 1; Type: header; Vendor: JST
J536 = EM,HDR,4P,1R,1x,picoblade: DigiKey: WM7608CT-ND; DigiReel: WM7608DKR-ND; Family: electro/mechanical; Index PN: 1523; Lead Style: SMT; MFG: Molex; Part Specific: CONN HEADER 4POS 1.25MM VERT SMD; Pin Cnt: 4; Pin Spacing: 1.25mm; Row Cnt: 1; Type: connector; Vendor: Molex
R73 = PAS,R,large: Resistor; ALT_SYMBOLS: 0402_1mm; CCA: 91; DigiKey: 311-10.0KLRCT-ND; DigiReel: 311-10.0KLRDKR-ND; Family: passive; ICA_MFR_NAME: PANASONIC; ICA_PARTNUM: $$1785048$$ERJ-3GSYJ102; Index PN: 680; Install: Y; Lead Style: SMT; MFG: Yageo; Material: chip; P/D_NUM: RC0402FR-0710KL; Part Number: RC0402FR-0710KL; Part Specific: RES 10K OHM 1% 1/16W 0402 SMD; Power: 1/16W; TOLERANCE: 1%; Type: resistor; VPC: 1/16W; Vendor: Yageo
R80 = PAS,R,large: DigiKey: P0.0ACT-ND; DigiReel: P0.0ADKR-ND; Family: passive; ICA_MFR_NAME: PANASONIC; ICA_PARTNUM: $$1785048$$ERJ-3GSYJ102; Index PN: 160; Install: Y; MFG: Panasonic; Material: chip; P/D_NUM: ERJ6GEY0R00V; Part Number: ERJ6GEY0R00V; Part Specific: RES 0.0 OHM 1/8W 0805 SMD 2A; Power: 1/8w; Type: resistor; VPC: 2A; Vendor: Panasonic
R81 = PAS,R,large: ALT_SYMBOLS: 0402_1mm; DigiKey: P1.00KLCT-ND; DigiReel: P1.00KLDKR-ND; Family: passive; Index PN: 684; Lead Style: SMT; MFG: Panasonic; Material: chip; P/D_NUM: ERJ-2RKF1001X; Part Number: ERJ-2RKF1001X; Part Specific: RES 1.00K OHM 1/10W 1% 0402 SMD; Power: 1/16W; TOLERANCE: 1%; Type: resistor; VENDOR: Panasonic; VPC: 1/16W
R133 R144 = PAS,R,large: ALT_SYMBOLS: 0402_1mm; DigiKey: A109548CT-ND; DigiReel: A109548DKR-ND; Family: passive; Lead Style: SMT; MFG: TE Connectivity; Material: chip; P/D_NUM: RLP73N1ER47FTDF; Part Number: RLP73N1ER47FTDF; Part Specific: RES 0.47 OHM 1% 1/8W 0402; Power: 1/8W; Tolerance: 1%; Type: resistor; VPC: 1/8W; Vendor: TE Connectivity
R134-R138 = PAS,R,large: ALT_SYMBOLS: 0402_1mm; DigiKey: P0.0JCT-ND; DigiReel: P0.0JDKR-ND; Family: passive; ICA_MFR_NAME: PANASONIC; ICA_PARTNUM: $$1785048$$ERJ-3GSYJ102; Index PN: 687; Install: Y; Lead Style: SMT; MFG: Panasonic; Material: chip; P/D_NUM: ERJ-2GE0R00X; Part Number: ERJ-2GE0R00X; Part Specific: RES 0.0 OHM 1/16W 0402 SMD; Power: 1/16W; Type: resistor; VPC: 1/16W; Vendor: Panasonic
R142 R143 R884 R885 = PAS,R,large: ALT_SYMBOLS: 0402_1mm; DigiKey: P3.3KJCT-ND; DigiReel: P3.3KJDKR-ND; Family: passive; Lead Style: SMT; MFG: Panasonic; Material: chip; P/D_NUM: ERJ-2GEJ332X; Part Number: ERJ-2GEJ332X; Part Specific: RES 3.3K OHM 5% 1/10W 0402 SMD; Tolerance: 5%; Type: resistor; VPC: 1/10W; Vendor: Panasonic
R145 = PAS,R,large: ALT_SYMBOLS: 0402_1mm; DigiKey: P0.0JCT-ND; DigiReel: P0.0JDKR-ND; Family: passive; ICA_MFR_NAME: PANASONIC; ICA_PARTNUM: $$1785048$$ERJ-3GSYJ102; Index PN: 687; Install: DNI; Lead Style: SMT; MFG: Panasonic; Material: chip; P/D_NUM: ERJ-2GE0R00X; Part Number: ERJ-2GE0R00X; Part Specific: RES 0.0 OHM 1/16W 0402 SMD; Power: 1/16W; Type: resistor; VPC: 1/16W; Vendor: Panasonic
TP208 TP210 = EM,TERM,TESTPOINT: DigiKey: 36-5012-ND; Family: electro/mechanical; Index PN: 1162; Install: DNI; Lead Style: TH; MFG: Keystone; P/D_NUM: 5012; Part Number: 5012; Part Specific: TEST POINT PC MULTI PURPOSE WHT .063inD hole; Type: terminal; Vendor: Keystone
TP209 TP211 = EM,TERM,TESTPOINT: DigiKey: SAM1029-01-ND; Family: electro/mechanical; Index PN: 896; Install: Y; Lead Style: TH; MFG: Samtec; P/D_NUM: TSW-101-07-G-S; Part Number: TSW-101-07-G-S; Part Specific: CONN HEADER 1POS .100in. SGL GOLD; Pin Cnt: 1; Pin Spacing: 100mil; Row Cnt: 1; Type: header; Vendor: Samtec
U35 = ANA,DRV,DRV8447,1x_3: DigiKey: 296-53424-1-ND; DigiReel: 296-53424-6-ND; Family: analog; Lead Style: SMT; MFG: Texas Instruments; P/D_NUM: DRV8847PWPR; Part Number: DRV8847PWPR; Part Specific: IC MOTOR DRVR DUAL H-BRIDGE 2A 16HTSSOP; Pin Cnt: 16; Type: motor driver; Vendor: Texas Instruments
U51 = LOG,BUF,74x16244: DigiKey: 296-1260-1-ND; Family: logic; Index PN: 110; Lead Style: SMT; MFG: Texas Instruments; P/D_NUM: SN74LVTH16244ADGG; Part Number: SN74LVTH16244ADGG; Part Specific: IC BUFF/DVR TRI-ST 16BIT 48TSSOP; Pin Spacing: 50mil; Vendor: Texas Instruments
U55 = LOG,OR,Tiny_Logic,small: DigiKey: 296-1093-1-ND; Family: logic; Index PN: 163; MFG: Texas Instruments; P/D_NUM: SN74AHC1G32DBVR; Part Number: SN74AHC1G32DBVR; Part Specific: tiny logic; Temp: C; Type: or; Vendor: Texas Instruments
C665 C692 C694 = PAS,CAP,NP: ALT_SYMBOLS: 0402_1mm; CCA: 9; DigiKey: 587-3499-1-ND; Family: passive; Index PN: 1280; Install: Y; Lead Style: SMT; MFG: Taiyo Yuden; Material: x5r; P/D_NUM: UMK105BJ104KV-F; Part Number: UMK105BJ104KV-F; Part Specific: CAP CER 0.1UF 50V 10% X5R 0402; TOLERANCE: 10%; Type: capacitor; VPC: 50V; Vendor: Taiyo Yuden
C687-C690 C695 C696 = PAS,CAP,NP: ALT_SYMBOLS: 0402_1mm; CCA: 34; DigiKey: 587-3499-1-ND; Family: passive; Index PN: 1280; Install: Y; Lead Style: SMT; MFG: Taiyo Yuden; Material: x5r; P/D_NUM: UMK105BJ104KV-F; Part Number: UMK105BJ104KV-F; Part Specific: CAP CER 0.1UF 50V 10% X5R 0402; TOLERANCE: 10%; Type: capacitor; VPC: 50V; Vendor: Taiyo Yuden
C691 C693 = PAS,CAP,NP: ALT_SYMBOLS: 0402_1mm; CCA: 9; DigiKey: 587-3499-1-ND; Family: passive; Index PN: 1280; Install: Y; Lead Style: SMT; MFG: Taiyo Yuden; Material: x5r; P/D_NUM: UMK105BJ104KV-F; Part Number: UMK105BJ104KV-F; Part Specific: CAP CER 0.1UF 50V 10% X5R 0402; RATING: <RATING>; TOLERANCE: 10%; Type: capacitor; VPC: 50V; Vendor: Taiyo Yuden
J102 = EM,CONN,DB9,ALT: DigiKey: 190-09FA-ND; Family: electro/mechanical; Index PN: 1457; Lead Style: SMT; MFG: NorComp; P/D_NUM: 190-009-263R001; Part Number: 190-009-263R001; Part Specific: CONN DSUB RCPT 9POS SMD R/A SLDR; Type: connector; Vendor: NorComp
J103-J105 = EM,HDR,6P,1R,1x,B6B-EH: DigiKey: 455-1661-ND; Family: electro/mechanical; Index PN: 1663; Lead Style: TH; MFG: JST; P/D_NUM: B6B-ZR(LF)(SN); Part Number: B6B-ZR(LF)(SN); Part Specific: CONN HEADER VERT 6POS 1.5MM; Pin Cnt: 6; Pin Spacing: 1.5mm; Row Cnt: 1; Type: header; Vendor: JST
J111-J113 = EM,HDR,6P,2R,1x: DigiKey: 952-2092-ND; Family: electro/mechanical; Index PN: 1539; Lead Style: TH; MFG: Harwin; P/D_NUM: M20-9950345; Part Number: M20-9950345; Part Specific: DIL HORIZ PC TAIL PIN HEADER Right Angle; Pin Cnt: 6; Row Cnt: 2; Type: header; Vendor: Harwin
R647-R649 = PAS,R,large: ALT_SYMBOLS: 0402_1mm; CCA: 65; DigiKey: 311-10.0KLRCT-ND; Family: passive; ICA_MFR_NAME: PANASONIC; ICA_PARTNUM: $$1785048$$ERJ-3GSYJ102; Index PN: 680; Install: Y; Lead Style: SMT; MFG: Yageo; Material: chip; P/D_NUM: RC0402FR-0710KL; Part Number: RC0402FR-0710KL; Power: 1/16W; TOLERANCE: 1%; Type: resistor; VPC: 1/16W; Vendor: Yageo
U46 = INF,DRVR,RS232,MAX3232E: DigiKey: 296-13096-1-ND; Family: interface; Index PN: 1493; Lead Style: SMT; MFG: Texas Instruments; Part Specific: IC DRVR/RCVR MLTCH RS232 16TSSOP; Type: driver; Vendor: Texas Instruments

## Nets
GND: C133.2 C136.2 C137.2 C141.2 C147.2 C320.2 C665.2 C666.1 C667.1 C668.2 C669.2 C677.2 C678.2 C679.2 C682.1 C683.1 C687.1 C688.1 C689.1 C690.1 C692.2 C694.2 C695.1 C696.1 J3.5 J3.6 J3.8 J3.10 J3.15 J3.19 J3.24 J3.27 J3.30 J3.33 J3.36 J3.39 J3.42 J3.45 J3.48 J3.51 J3.52(GND) J3.53(GND) J3.54(GND) J3.55(GND) J3.56(GND) J3.57(GND) J3.58(GND) J3.59(GND) J3.60(GND) J3.61(GND) J3.62(GND) J3.63(GND) J7.1 J7.4 J7.5 J7.8 J7.9 J7.12 J7.13 J7.16 J7.17 J7.20 J7.21 J7.24 J7.25 J7.28 J7.29 J7.32 J7.33 J7.36 J7.39 J7.42 J7.52(GND) J7.53(GND) J7.54(GND) J7.55(GND) J7.56(GND) J7.57(GND) J7.58(GND) J7.59(GND) J7.60(GND) J7.61(GND) J7.62(GND) J7.63(GND) J10.1 J10.4 J10.5 J10.8 J10.9 J10.12 J10.13 J10.16 J10.17 J10.20 J10.21 J10.24 J10.25 J10.28 J10.29 J10.32 J10.33 J10.36 J10.39 J10.42 J10.50 J10.51 J10.52(GND) J10.53(GND) J10.54(GND) J10.55(GND) J10.56(GND) J10.57(GND) J10.58(GND) J10.59(GND) J10.60(GND) J10.61(GND) J10.62(GND) J10.63(GND) J17.8(P8) J17.13(P13) J17.14(P14) J102.5 J103.1 J104.1 J105.1 J110.1 J110.14 J111.6(P6) J112.6(P6) J113.6(P6) J120.6 J120.10 J120.11 J120.12 J121.6 J121.10 J121.11 J121.12 J122.7 J536.4 R120.2(N2) R133.2(N2) R138.2(N2) R144.2(N2) R145.2(N2) R648.2(N2) R649.2(N2) U4.33(GND) U4.52(GND) U8.33(GND) U8.52(GND) U15.E20(VX1_CM_CKREF0) U15.E21(VX1_CM_CKREF1) U15.E23(VX1_CM_CKREF2) U15.E24(VX1_CM_CKREF3) U35.13(GND) U35.17(PAD) U46.15(GND) U51.1(1~{OE}) U51.4(GND) U51.10(GND) U51.15(GND) U51.21(GND) U51.24(4~{OE}) U51.25(3~{OE}) U51.26(4A4) U51.27(4A3) U51.28(GND) U51.34(GND) U51.39(GND) U51.45(GND) U51.48(2~{OE}) U55.3(GND) ; also on sheet 3 4 5 6 7 8 9 10 18 19 20 21 22 23 25 26
P5V: J67.1 ; also on sheet 3 10 25
P5V_Vx1_FE: J3.1 J3.2 J3.3 J3.4 J67.2
P12V: J120.1 J120.2 J121.1 J121.2 R80.2(N2) R246.1(N1) ; also on sheet 7 21 25
P12V_DRV: C133.1 C320.1 R80.1(N1) U35.12(VM)
ACT_A_CIPO: J120.4 U51.3(1Y2)
ACT_A_CLK: J120.5 U51.5(1Y3)
ACT_A_COPI: J120.3 U51.2(1Y1)
ACT_B_CIPO: J120.8 U51.8(2Y1)
ACT_B_CLK: J120.9 U51.9(2Y2)
ACT_B_COPI: J120.7 U51.6(1Y4)
ACT_C_CIPO: J121.4 U51.12(2Y4)
ACT_C_CLK: J121.5 U51.13(3Y1)
ACT_C_COPI: J121.3 U51.11(2Y3)
ACT_D_CIPO: J121.8 U51.16(3Y3)
ACT_D_CLK: J121.9 U51.17(3Y4)
ACT_D_COPI: J121.7 U51.14(3Y2)
AISEN: R144.1(N1) U35.3(AISEN)
AW0_DAC_ENz: R653.1(N1) R654.1(N1) TP208.1(P1) U51.30(4A1)
AW1_DAC_ENz: R651.1(N1) R652.1(N1) TP210.1(P1) U51.29(4A2)
AW_DAC_ENz: R652.2(N2) R653.2(N2) U55.4(Y)
AWC0_DACCLK_0_1: J110.3 U51.40(2A2) U51.44(1A3) ; also on sheet 20
AWC0_DACD_PWMB_0: J110.5 R135.2(N2) U51.47(1A1) ; also on sheet 20
AWC0_DACD_PWMB_1: J110.7 U51.43(1A4) ; also on sheet 20
AWC0_DACS_PWMA_0: J110.4 R134.2(N2) U51.46(1A2) ; also on sheet 20
AWC0_DACS_PWMA_1: J110.6 U51.41(2A1) ; also on sheet 20
AWC0_OUT_ENZ: J110.2 R654.2(N2) U55.1(A) ; also on sheet 20
AWC0_PWMA_0: R134.1(N1) U35.16(AIN1)
AWC0_PWMB_0: R135.1(N1) U35.15(AIN2)
AWC1_DACCLK_0_1: J110.9 U51.32(3A4) U51.36(3A1) ; also on sheet 20
AWC1_DACD_PWMB_0: J110.11 R137.2(N2) U51.38(2A3) ; also on sheet 20
AWC1_DACD_PWMB_1: J110.13 U51.35(3A2) ; also on sheet 20
AWC1_DACS_PWMA_0: J110.10 R136.2(N2) U51.37(2A4) ; also on sheet 20
AWC1_DACS_PWMA_1: J110.12 U51.33(3A3) ; also on sheet 20
AWC1_OUT_ENZ: J110.8 R651.2(N2) U55.2(B) ; also on sheet 20
AWC1_PWMA_0: R136.1(N1) U35.9(BIN1)
AWC1_PWMB_0: R137.1(N1) U35.10(BIN2)
BISEN: R133.1(N1) U35.6(BISEN)
COIL_AOUT1: C134.1 J14.1 J17.1(P1) U35.2(AOUT1)
COIL_AOUT2: C134.2 J14.2 J17.2(P2) U35.4(AOUT2)
COIL_BOUT1: C135.1 J15.1 J17.3(P3) U35.7(BOUT1)
COIL_BOUT2: C135.2 J15.2 J17.4(P4) U35.5(BOUT2)
DAC_EN0z: J122.1 TP209.1(P1) U51.19(4Y1)
DAC_EN1z: J122.2 TP211.1(P1) U51.20(4Y2)
DMD1_SPARE_43: J10.43 R670.1(N1) R671.1(N1)
DMD_DEN_ARSTZ: J7.43 R120.1(N1) R670.2(N2) U15.AK12(DMD_DEN_ARSTZ)
DMD_DMUX0: R671.2(N2) ; also on sheet 20
DMD_HSSI0_CLK_N: J7.18 U15.AJ25(DMD_HSSI0_CLK_N)
DMD_HSSI0_CLK_P: J7.19 U15.AK25(DMD_HSSI0_CLK_P)
DMD_HSSI0_N_0: J7.34 U15.AJ29(DMD_HSSI0_N_0)
DMD_HSSI0_N_1: J7.30 U15.AG28(DMD_HSSI0_N_1)
DMD_HSSI0_N_2: J7.26 U15.AJ27(DMD_HSSI0_N_2)
DMD_HSSI0_N_3: J7.22 U15.AG26(DMD_HSSI0_N_3)
DMD_HSSI0_N_4: J7.14 U15.AG24(DMD_HSSI0_N_4)
DMD_HSSI0_N_5: J7.10 U15.AJ23(DMD_HSSI0_N_5)
DMD_HSSI0_N_6: J7.6 U15.AG22(DMD_HSSI0_N_6)
DMD_HSSI0_N_7: J7.2 U15.AJ21(DMD_HSSI0_N_7)
DMD_HSSI0_P_0: J7.35 U15.AK29(DMD_HSSI0_P_0)
DMD_HSSI0_P_1: J7.31 U15.AH28(DMD_HSSI0_P_1)
DMD_HSSI0_P_2: J7.27 U15.AK27(DMD_HSSI0_P_2)
DMD_HSSI0_P_3: J7.23 U15.AH26(DMD_HSSI0_P_3)
DMD_HSSI0_P_4: J7.15 U15.AH24(DMD_HSSI0_P_4)
DMD_HSSI0_P_5: J7.11 U15.AK23(DMD_HSSI0_P_5)
DMD_HSSI0_P_6: J7.7 U15.AH22(DMD_HSSI0_P_6)
DMD_HSSI0_P_7: J7.3 U15.AK21(DMD_HSSI0_P_7)
DMD_HSSI1_CLK_N: J10.18 U15.AG7(DMD_HSSI1_CLK_N)
DMD_HSSI1_CLK_P: J10.19 U15.AH7(DMD_HSSI1_CLK_P)
DMD_HSSI1_N_0: J10.34 U15.AG11(DMD_HSSI1_N_0)
DMD_HSSI1_N_1: J10.30 U15.AJ10(DMD_HSSI1_N_1)
DMD_HSSI1_N_2: J10.26 U15.AG9(DMD_HSSI1_N_2)
DMD_HSSI1_N_3: J10.22 U15.AJ8(DMD_HSSI1_N_3)
DMD_HSSI1_N_4: J10.14 U15.AJ6(DMD_HSSI1_N_4)
DMD_HSSI1_N_5: J10.10 U15.AG5(DMD_HSSI1_N_5)
DMD_HSSI1_N_6: J10.6 U15.AJ4(DMD_HSSI1_N_6)
DMD_HSSI1_N_7: J10.2 U15.AJ2(DMD_HSSI1_N_7)
DMD_HSSI1_P_0: J10.35 U15.AH11(DMD_HSSI1_P_0)
DMD_HSSI1_P_1: J10.31 U15.AK10(DMD_HSSI1_P_1)
DMD_HSSI1_P_2: J10.27 U15.AH9(DMD_HSSI1_P_2)
DMD_HSSI1_P_3: J10.23 U15.AK8(DMD_HSSI1_P_3)
DMD_HSSI1_P_4: J10.15 U15.AK6(DMD_HSSI1_P_4)
DMD_HSSI1_P_5: J10.11 U15.AH5(DMD_HSSI1_P_5)
DMD_HSSI1_P_6: J10.7 U15.AK4(DMD_HSSI1_P_6)
DMD_HSSI1_P_7: J10.3 U15.AK2(DMD_HSSI1_P_7)
DMD_LS0_CLK_N: J7.41 U15.AG17(DMD_LS0_CLK_N)
DMD_LS0_CLK_P: J7.40 U15.AH17(DMD_LS0_CLK_P)
DMD_LS0_RDATA: J7.44 U15.AH13(DMD_LS0_RDATA)
DMD_LS0_WDATA_N: J7.38 U15.AJ16(DMD_LS0_WDATA_N)
DMD_LS0_WDATA_P: J7.37 U15.AK16(DMD_LS0_WDATA_P)
DMD_LS1_CLK_N: J10.41 U15.AG15(DMD_LS1_CLK_N)
DMD_LS1_CLK_P: J10.40 U15.AH15(DMD_LS1_CLK_P)
DMD_LS1_RDATA: J10.44 U15.AG13(DMD_LS1_RDATA)
DMD_LS1_WDATA_N: J10.38 U15.AJ14(DMD_LS1_WDATA_N)
DMD_LS1_WDATA_P: J10.37 U15.AK14(DMD_LS1_WDATA_P)
DMD_P1P8V_EN: J10.49 TP284.1(P1) ; also on sheet 20
DMD_P12V: C668.1 C669.1 C677.1 C678.1 C679.1 J7.46 J7.47 J7.48 J7.49 J7.50 J7.51 R246.2(N2)
DMD_PWR_EN: J7.45 J10.45 ; also on sheet 20
DRV_MODE: R145.1(N1) U35.14(MODE)
DRV_TRQ: R138.1(N1) U35.11(TRQ)
FE_3D_LR: J3.21 ; also on sheet 3 20
FE_PROJ_ON: J68.1 ; also on sheet 21
FE_SPR1: J3.13 TP7.1(P1)
HDMI_CEC: J3.23 ; also on sheet 3 20
HTPDN: J3.25 TP5.1(P1) U15.E17(VX1_HTPDN)
IIC0_SCL: J3.18 ; also on sheet 4 5 18 19 26
IIC0_SDA: J3.20 ; also on sheet 4 5 18 19 26
IIC1_SCL: J3.14 ; also on sheet 19 20 26
IIC1_SDA: J3.16 ; also on sheet 19 20 26
IIC2_SCL: J17.7(P7) J536.1 R142.1(N1) R885.1(N1) ; also on sheet 20
IIC2_SDA: J17.6(P6) J536.2 R143.1(N1) R884.1(N1) ; also on sheet 20
IIC_BUSY: J3.17 ; also on sheet 3 4 5 20
LOCKN: D1.1(CATHODE) J3.26 R9.1(N1) TP3.1(P1) U15.E19(VX1_LOCKN)
LOCKN_LED: D1.2(ANODE) R10.1(N1)
NFAULT: R73.2(N2) U35.8(nFAULT)
NSLEEP: R81.1(N1) U35.1(nSLEEP)
P3P3V: C136.1 C137.1 C141.1 C147.1 C665.1 C666.2 C667.2 C682.2 C683.2 C687.2 C688.2 C689.2 C690.2 C695.2 C696.2 J17.5(P5) J103.3 J104.3 J105.3 J111.1(P1) J112.1(P1) J113.1(P1) J536.3 R9.2(N2) R10.2(N2) R73.1(N1) R81.2(N2) R84.1(N1) R85.1(N1) R86.1(N1) R89.2(N2) R92.1(N1) R93.1(N1) R94.1(N1) R98.1(N1) R102.2(N2) R142.2(N2) R143.2(N2) R647.1(N1) R884.2(N2) R885.2(N2) U4.29(VCCIO) U4.43(VCC) U8.29(VCCIO) U8.43(VCC) U46.16(VCC) U51.7(VCC) U51.18(VCC) U51.31(VCC) U51.42(VCC) U55.5(VCC) ; also on sheet 4 6 7 8 9 10 18 19 20 21 22 25 26
PM0_BYTEZ: R89.1(N1) U4.53(BYTE#)
PM0_RY_BYZ: TP8.1(P1) U4.17(RY/~{BY})
PM0_WPZ: R85.2(N2) U4.16(~{WP})
PM1_BYTEZ: R102.1(N1) U8.53(BYTE#)
PM1_RY_BYZ: TP12.1(P1) U8.17(RY/~{BY})
PM1_WPZ: R92.2(N2) U8.16(~{WP})
PM_ADDR_0: U4.31(A0) U8.31(A0) U15.T30(PM_ADDR_0)
PM_ADDR_1: U4.26(A1) U8.26(A1) U15.U26(PM_ADDR_1)
PM_ADDR_2: U4.25(A2) U8.25(A2) U15.U27(PM_ADDR_2)
PM_ADDR_3: U4.24(A3) U8.24(A3) U15.U29(PM_ADDR_3)
PM_ADDR_4: U4.23(A4) U8.23(A4) U15.U30(PM_ADDR_4)
PM_ADDR_5: U4.22(A5) U8.22(A5) U15.V29(PM_ADDR_5)
PM_ADDR_6: U4.21(A6) U8.21(A6) U15.V28(PM_ADDR_6)
PM_ADDR_7: U4.20(A7) U8.20(A7) U15.V27(PM_ADDR_7)
PM_ADDR_8: U4.10(A8) U8.10(A8) U15.V26(PM_ADDR_8)
PM_ADDR_9: U4.9(A9) U8.9(A9) U15.W30(PM_ADDR_9)
PM_ADDR_10: U4.8(A10) U8.8(A10) U15.W29(PM_ADDR_10)
PM_ADDR_11: U4.7(A11) U8.7(A11) U15.W28(PM_ADDR_11)
PM_ADDR_12: U4.6(A12) U8.6(A12) U15.W26(PM_ADDR_12)
PM_ADDR_13: U4.5(A13) U8.5(A13) U15.Y30(PM_ADDR_13)
PM_ADDR_14: U4.4(A14) U8.4(A14) U15.Y29(PM_ADDR_14)
PM_ADDR_15: U4.3(A15) U8.3(A15) U15.Y28(PM_ADDR_15)
PM_ADDR_16: U4.54(A16) U8.54(A16) U15.Y27(PM_ADDR_16)
PM_ADDR_17: U4.19(A17) U8.19(A17) U15.Y26(PM_ADDR_17)
PM_ADDR_18: U4.18(A18) U8.18(A18) U15.AA30(PM_ADDR_18)
PM_ADDR_19: U4.11(A19) U8.11(A19) U15.AA29(PM_ADDR_19)
PM_ADDR_20: U4.12(A20) U8.12(A20) U15.AA27(PM_ADDR_20)
PM_ADDR_21: U4.15(A21) U8.15(A21) U15.AA26(PM_ADDR_21)
PM_ADDR_22: U4.2(A22) U8.2(A22) U15.AB29(PM_ADDR_22)
PM_ADDR_23: U4.1(A23) U8.1(A23) ; also on sheet 20
PM_CSZ_0: R84.2(N2) U4.32(~{CE}) U15.T27(PM_CSZ_0)
PM_CSZ_1: R93.2(N2) U8.32(~{CE}) U15.T28(PM_CSZ_1)
PM_DATA_0: U4.35(DQ0) U8.35(DQ0) U15.L29(PMDATA_00)
PM_DATA_1: U4.37(DQ1) U8.37(DQ1) U15.L30(PMDATA_01)
PM_DATA_2: U4.39(DQ2) U8.39(DQ2) U15.L28(PMDATA_02)
PM_DATA_3: U4.41(DQ3) U8.41(DQ3) U15.M27(PMDATA_03)
PM_DATA_4: U4.44(DQ4) U8.44(DQ4) U15.M28(PMDATA_04)
PM_DATA_5: U4.46(DQ5) U8.46(DQ5) U15.M29(PMDATA_05)
PM_DATA_6: U4.48(DQ6) U8.48(DQ6) U15.M30(PMDATA_06)
PM_DATA_7: U4.50(DQ7) U8.50(DQ7) U15.N26(PMDATA_07)
PM_DATA_8: U4.36(DQ8) U8.36(DQ8) U15.N27(PMDATA_08)
PM_DATA_9: U4.38(DQ9) U8.38(DQ9) U15.N29(PMDATA_09)
PM_DATA_10: U4.40(DQ10) U8.40(DQ10) U15.N30(PMDATA_10)
PM_DATA_11: U4.42(DQ11) U8.42(DQ11) U15.P26(PMDATA_11)
PM_DATA_12: U4.45(DQ12) U8.45(DQ12) U15.P27(PMDATA_12)
PM_DATA_13: U4.47(DQ13) U8.47(DQ13) U15.P28(PMDATA_13)
PM_DATA_14: U4.49(DQ14) U8.49(DQ14) U15.P29(PMDATA_14)
PM_DATA_15: U4.51(DQ15) U8.51(DQ15) U15.R26(PMDATA_15)
PM_OEZ: R94.2(N2) U4.34(~{OE}) U8.34(~{OE}) U15.R29(PM_OEZ)
PM_WEZ: R98.2(N2) R112.1(N1) U4.13(~{WE}) U8.13(~{WE})
PM_WEZ_T: R112.2(N2) U15.R28(PM_WEZ)
POSENSE: R86.2(N2) U4.14(~{RESET}) U8.14(~{RESET}) ; also on sheet 8 9 10 18 21
RS232_VN: C694.1 U46.6(V-)
RX0N: C72.2 J3.49
RX0P: C73.2 J3.50
RX1N: C67.2 J3.46
RX1P: C68.2 J3.47
RX2N: C65.2 J3.43
RX2P: C66.2 J3.44
RX3N: C63.2 J3.40
RX3P: C64.2 J3.41
RX4N: C61.2 J3.37
RX4P: C62.2 J3.38
RX5N: C53.2 J3.34
RX5P: C54.2 J3.35
RX6N: C49.2 J3.28
RX6P: C50.2 J3.29
RX7N: C51.2 J3.31
RX7P: C52.2 J3.32
SPI0_CIPO: J122.6 ; also on sheet 9 18 19
SPI0_CLK: J122.5 ; also on sheet 9 18 19
SPI0_COPI: J122.4 ; also on sheet 9 18 19
SPI0_CSZ_1: J122.3 ; also on sheet 18
SPI1_CIPO: J3.9 ; also on sheet 19 20
SPI1_CLK: J3.7 ; also on sheet 19 20
SPI1_COPI: J3.11 ; also on sheet 19 20
SPI1_CSZ_0: J3.12 ; also on sheet 19 20
UART0_C1M: C691.1 U46.3(C1-)
UART0_C1P: C691.2 U46.1(C1+)
UART0_C2M: C693.1 U46.5(C2-)
UART0_C2P: C693.2 U46.4(C2+)
UART0_CTSZ: J94.1 J104.2 J112.4(P4) ; also on sheet 18
UART0_CTSZ_CON: J102.7 U46.13(R_IN1)
UART0_CTSZ_JUMPER: J94.2 R649.1(N1) U46.12(R_OUT1)
UART0_DCD_CON: J102.1 R668.1(N1)
UART0_DSR_CON: J102.6 R650.2(N2) R668.2(N2)
UART0_DTR_CON: J102.4 R650.1(N1)
UART0_RSTZ_CON: J102.8 U46.14(T_OUT1)
UART0_RTSZ: J104.6 J112.5(P5) R648.1(N1) U46.11(T_IN1) ; also on sheet 18
UART0_RXD: J95.1 J104.5 J112.3(P3) ; also on sheet 18
UART0_RXD_CON: J102.3 U46.8(R_IN2)
UART0_RXD_JUMPER: J95.2 U46.9(R_OUT2)
UART0_TXD: J104.4 J112.2(P2) R647.2(N2) U46.10(T_IN2) ; also on sheet 18
UART0_TXD_CON: J102.2 U46.7(T_OUT2)
UART0_VP: C692.1 U46.2(V+)
UART1_CTSZ: J105.2 J113.4(P4) ; also on sheet 20
UART1_RTSZ: J105.6 J113.5(P5) ; also on sheet 20
UART1_RXD: J105.5 J113.3(P3) ; also on sheet 20
UART1_TXD: J105.4 J113.2(P2) ; also on sheet 20
UART2_RXD: J103.5 J111.3(P3) ; also on sheet 20
UART2_TXD: J103.4 J111.2(P2) ; also on sheet 20
VBIAS_MON: J10.47 TP285.1(P1) ; also on sheet 20
VX1_DATA0_N: C72.1 U15.D18(VX1_DATA0_N)
VX1_DATA0_P: C73.1 U15.C18(VX1_DATA0_P)
VX1_DATA1_N: C67.1 U15.B19(VX1_DATA1_N)
VX1_DATA1_P: C68.1 U15.A19(VX1_DATA1_P)
VX1_DATA2_N: C65.1 U15.D20(VX1_DATA2_N)
VX1_DATA2_P: C66.1 U15.C20(VX1_DATA2_P)
VX1_DATA3_N: C63.1 U15.B21(VX1_DATA3_N)
VX1_DATA3_P: C64.1 U15.A21(VX1_DATA3_P)
VX1_DATA4_N: C61.1 U15.D22(VX1_DATA4_N)
VX1_DATA4_P: C62.1 U15.C22(VX1_DATA4_P)
VX1_DATA5_N: C53.1 U15.B23(VX1_DATA5_N)
VX1_DATA5_P: C54.1 U15.A23(VX1_DATA5_P)
VX1_DATA6_N: C49.1 U15.D24(VX1_DATA6_N)
VX1_DATA6_P: C50.1 U15.C24(VX1_DATA6_P)
VX1_DATA7_N: C51.1 U15.B25(VX1_DATA7_N)
VX1_DATA7_P: C52.1 U15.A25(VX1_DATA7_P)
Vx1_PROJ_ON: J3.22 J68.2

Not connected (* = marked no-connect by the designer): J10 46* 48*; J17 9(P9)* 10(P10)* 11(P11)* 12(P12)*; J102 9*; J103 2* 6*; J111 4(P4)* 5(P5)*; U4 27(NC3)* 28(NC4)* 30(NC6)* 55(NC2)* 56(NC1)*; U8 27(NC3)* 28(NC4)* 30(NC6)* 55(NC2)* 56(NC1)*; U15 AJ12(HSSI_ATETEST)* R30(PM_BLSZ_0)* T26(PM_BLSZ_1)* T29(PM_CSZ_2)*; U51 22(4Y3)* 23(4Y4)*

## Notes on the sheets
sheet 11
- (C) COPYRIGHT 2020
         Texas Instruments
        All Rights Reserved
sheet 12
- Place Caps
  C134 & C1335
  near J17
  connector pins.
- Actuator Option #1:
  Install R80
  Actuator Option #2:
  Remove R80
- R145 DNI: Independent Bridge
  Interface Mode (Default)
  R145 Installed: 4-Pin Interface
  Mode
- Actuator Option #1:
   Install R134, R135
            R136 & R137
- Actuator Coil
  Pins Access
  Points
- External Actuator Driver Board I/F
- Actuator Board Interface
- For Cable to Actuator driver:
  -  Do not connect J122 pin 3.
- Probe Points
- Actuator Driver - H-Bridge Driver & Current Driver I/F
- (C) COPYRIGHT 2020
         Texas Instruments
        All Rights Reserved
sheet 13
- COMPUTER GENERATED DRAWING - DO NOT REVISE MANUALLY
- INDEX
- REVISIONS
- P01 - TITLE PAGE
  P02 - REVISION HISTORY
  P03 - BLOCK DIAGRAM
  P04 - DLPC VX1 INPUT INTERFACE
  P05 - DLPC FPDlink/Parallel ln
  P06- DLPC MEMORY INTERFACE
  P07 - DLPC DMD INTERFACE
  P08 - DLPC MISC
  P09 - DLPC GPIO
  P10 - DLPC PWR
  P11 - DLPC GND & NC
  P12 - IIC, SPI, USB & EEPROM
  P13 - DLPC Core Pwr
  P14 - Actuator Driver
  P15 - DLPA100 #0
  P16 - DLPA100 #1
  P17 - DLPA100 #2
  P18 - DLPC SSI DRVR I/F
  P19 - VIN & POWER SEQ
  P20 - RS232
  P21 - Ballast Connection
  P22 - Cypress
  P23 - Keypad, MSP430
  P24 - FPDlink-Parallel In Connect
  P25 - HARDWARE
  P26 - IMPORTANT NOTICE
- REV
- DESCRIPTION
- DATE
- APPROVED
- A
- Initial Release - Based off Pico E.2
- B
- Updates per DLPC7540EVM_Design_Job Request_v1.2
- 18-Mar-2021
- C
- REFER REVISION HISTORY NOTES
- 12-Apr-2021
- DLPC7540EVM FORMATTER BOARD
- STATUS LEDs
- PAGE
- D1   - LOCKN (low = led on)
  D15 - HEARTBEAT (low = led on)
  D5   - PWRGOOD (high = led on)
  D6   - FAULT (low = led on)
  D7   - PROJ_ON (high = led on)
  D8   - POSENSE (low = led on)
- 4
  9
  13
  9
  13
  13
- Cadence Capture V.17.2
sheet 14
- Block Diagram
- (C) COPYRIGHT 2020
         Texas Instruments
        All Rights Reserved
sheet 15
- IIC0 DLPC7540 IS SECONDARY
- IIC1 DLPC7540 IS PRIMARY
- SPI1 DLPC7540 IS SECONDARY
- PLACE DC BLOCKING CAPS
  CLOSE TO DLPC7540
- DLPC7540 Vx1 Input Interface
- (C) COPYRIGHT 2020
         Texas Instruments
        All Rights Reserved
sheet 16
- BOOT FLASH
- Flash Memory Interface
- (C) COPYRIGHT 2020
         Texas Instruments
        All Rights Reserved
sheet 17
- Cable
  Insertion
  Direction
- DMD Interface
- (C) COPYRIGHT 2020
         Texas Instruments
        All Rights Reserved
